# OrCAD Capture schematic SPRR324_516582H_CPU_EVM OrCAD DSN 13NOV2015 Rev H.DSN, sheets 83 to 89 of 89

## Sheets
83 SH14 - VAYU SD/MMC IF: size B; rev: A
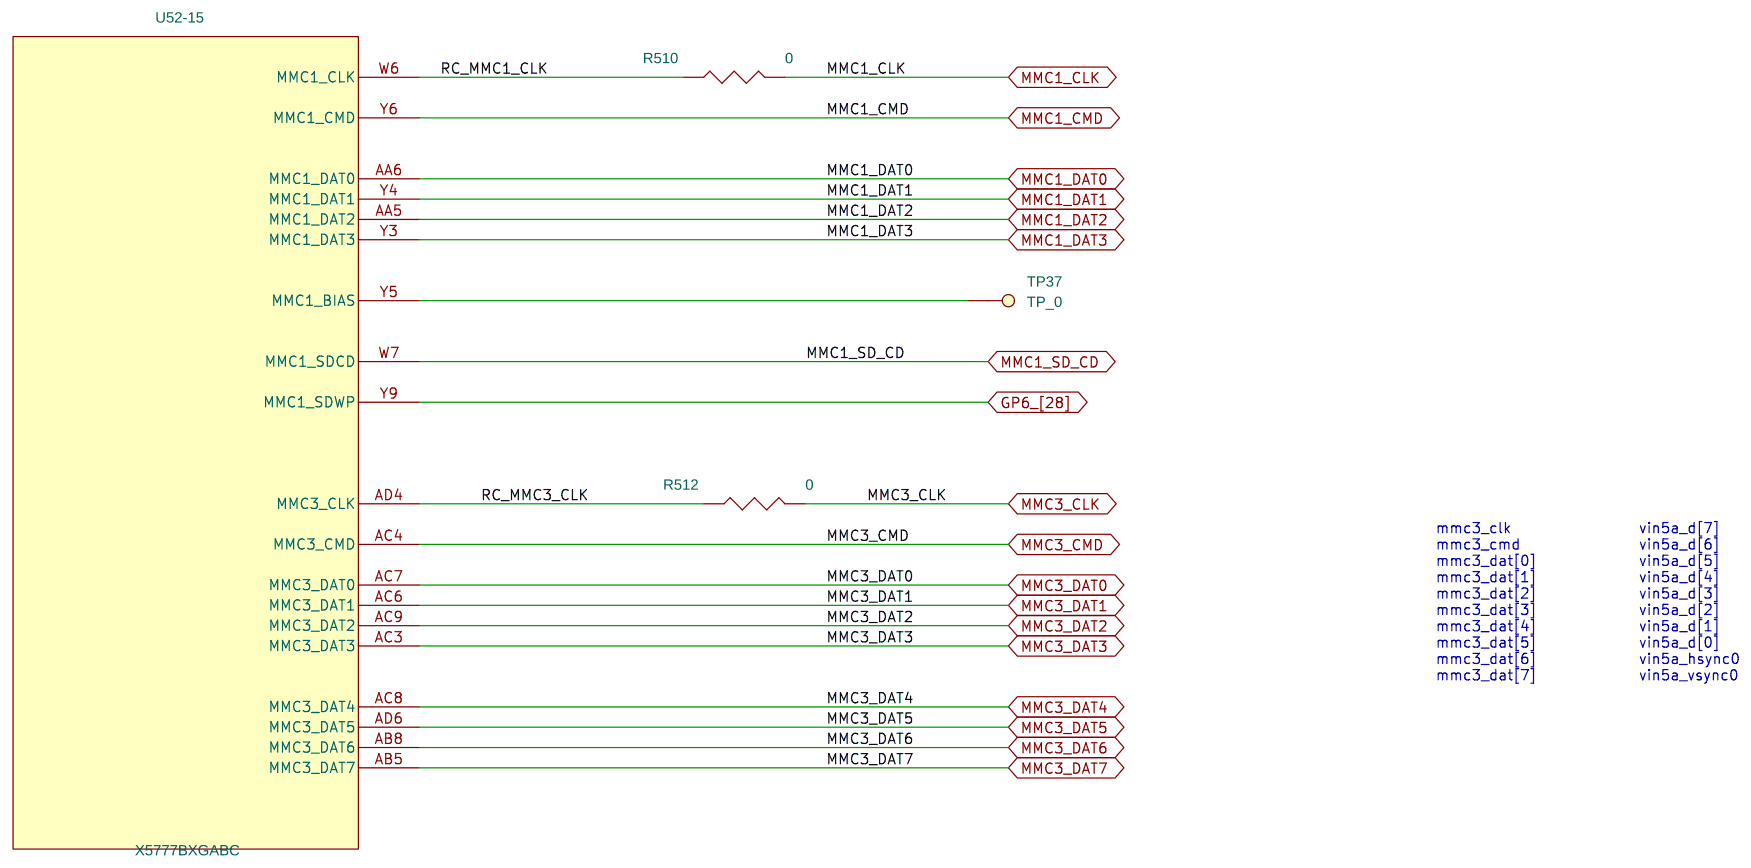
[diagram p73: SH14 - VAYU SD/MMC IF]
84 SH05 - SERIAL I/O MUX: size B; rev: E
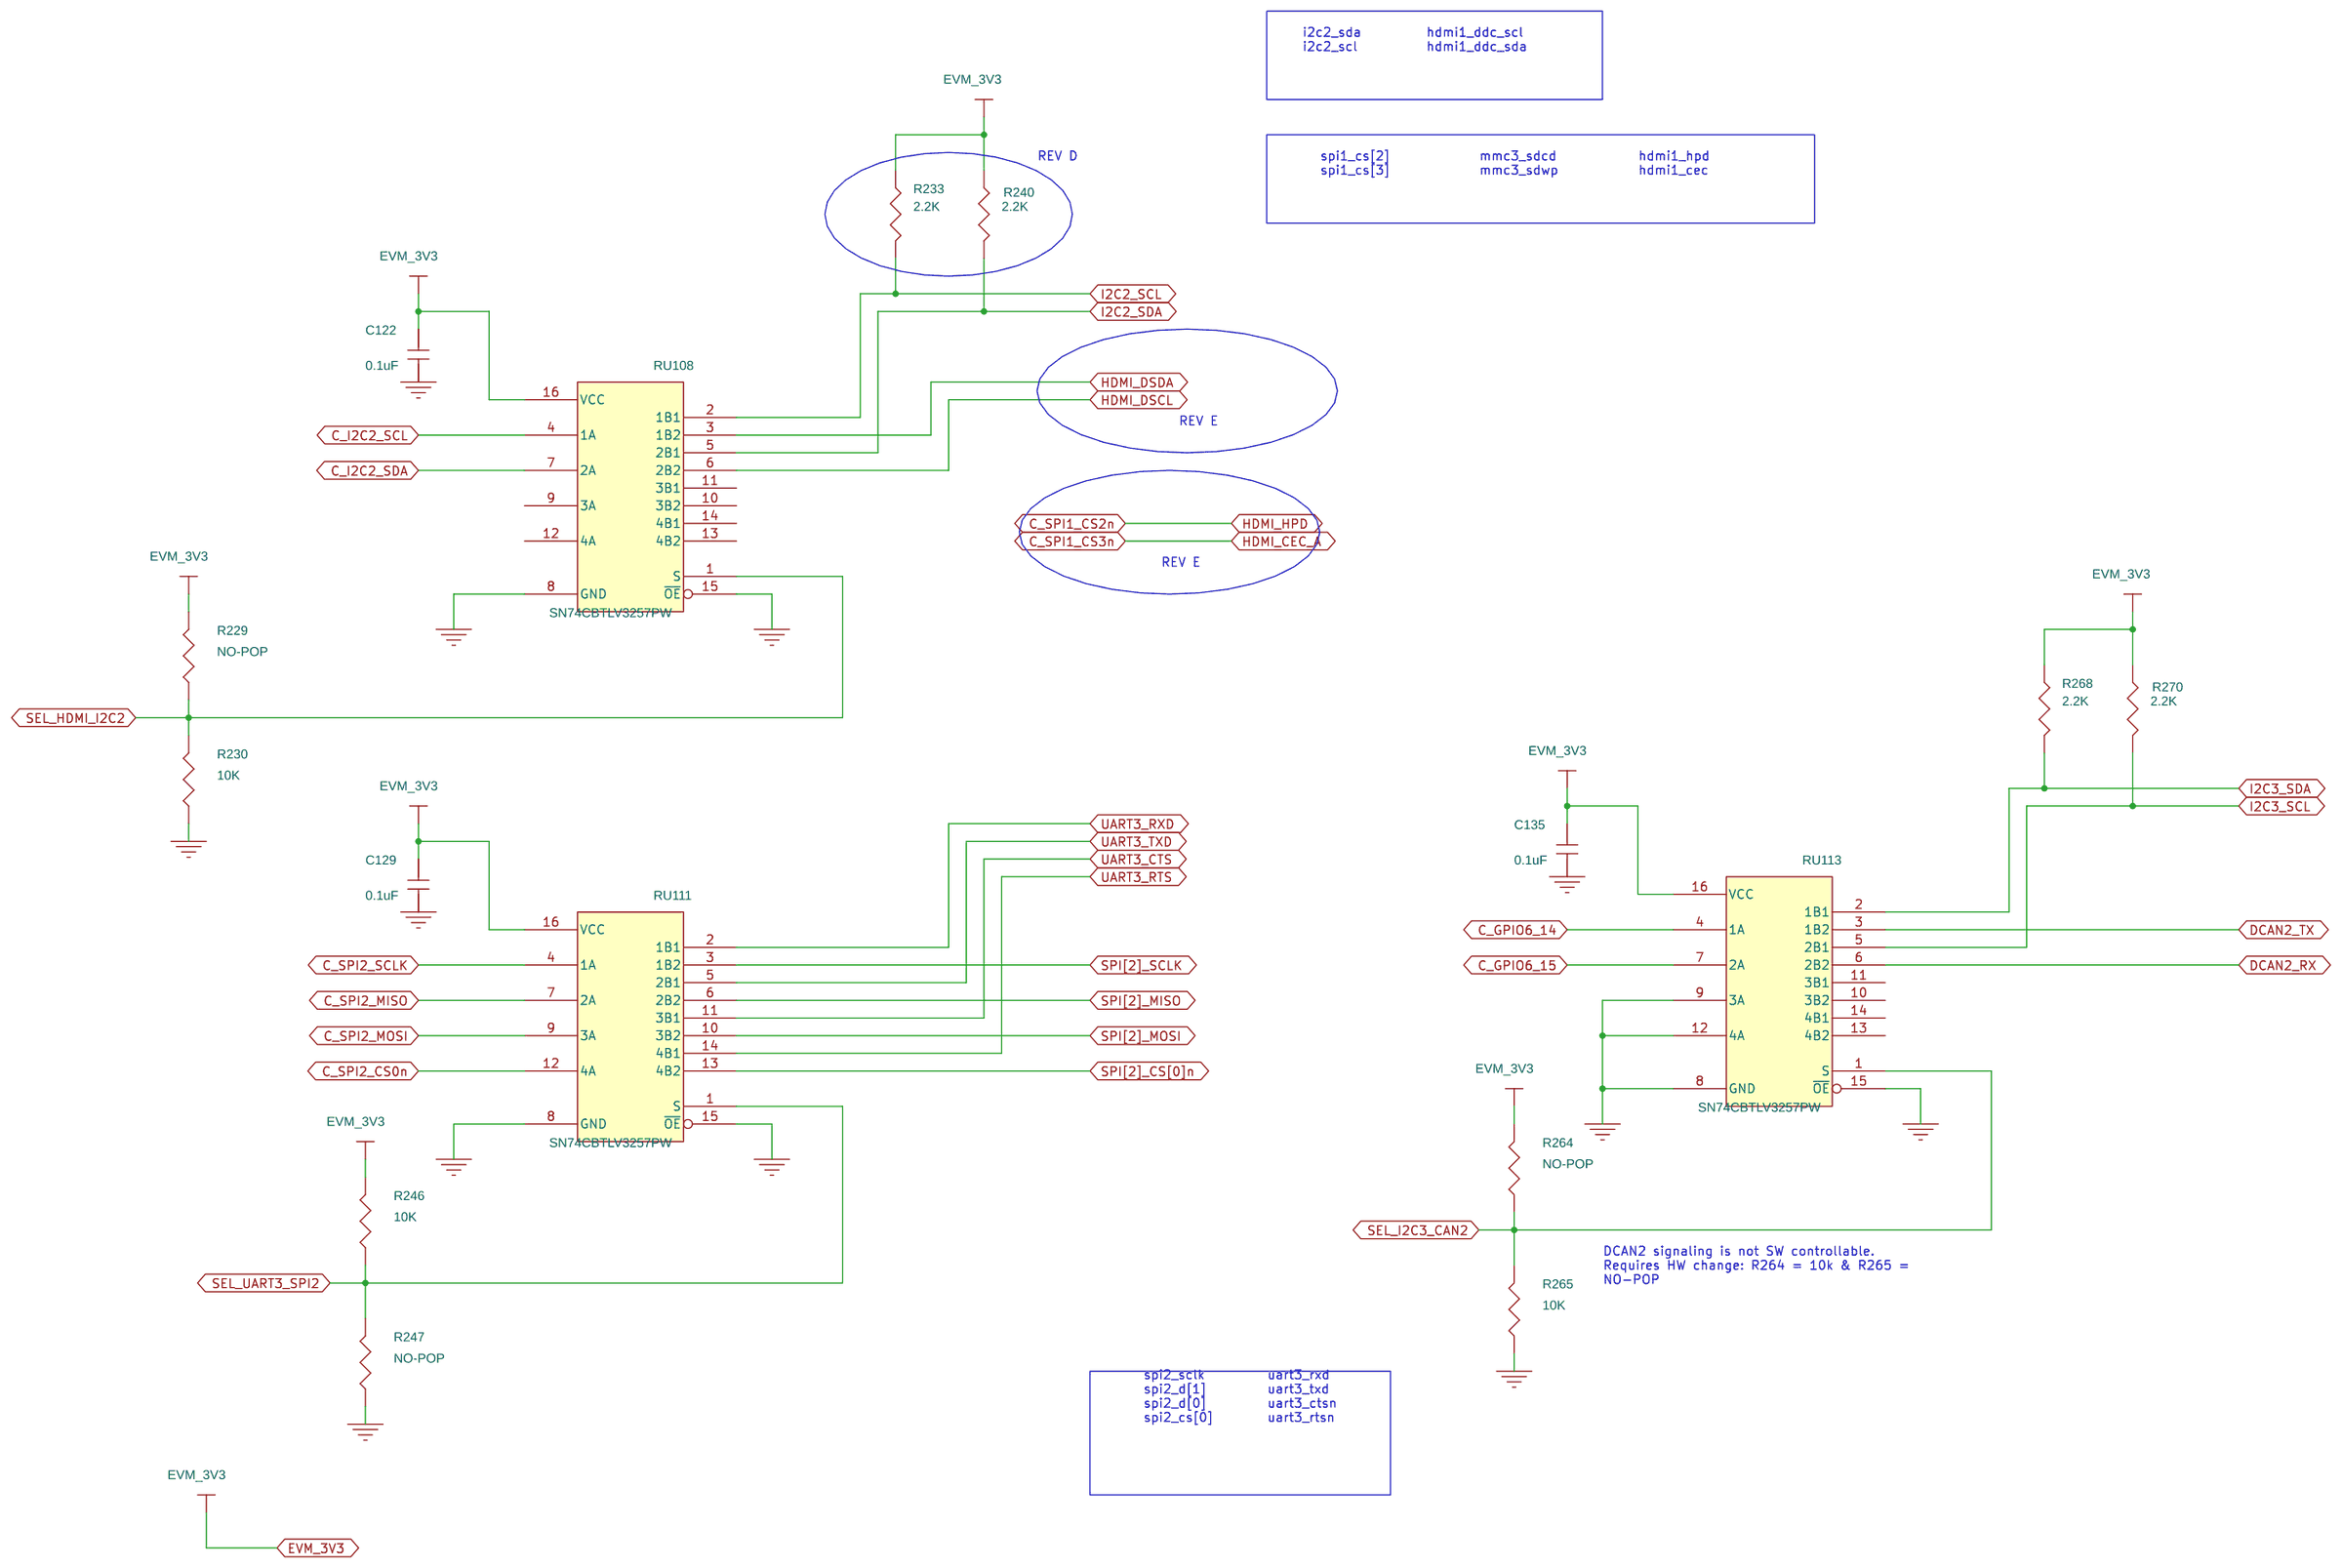
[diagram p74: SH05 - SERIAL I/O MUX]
85 SH18 - ENET0/VIN4 MUX: size B; rev: A
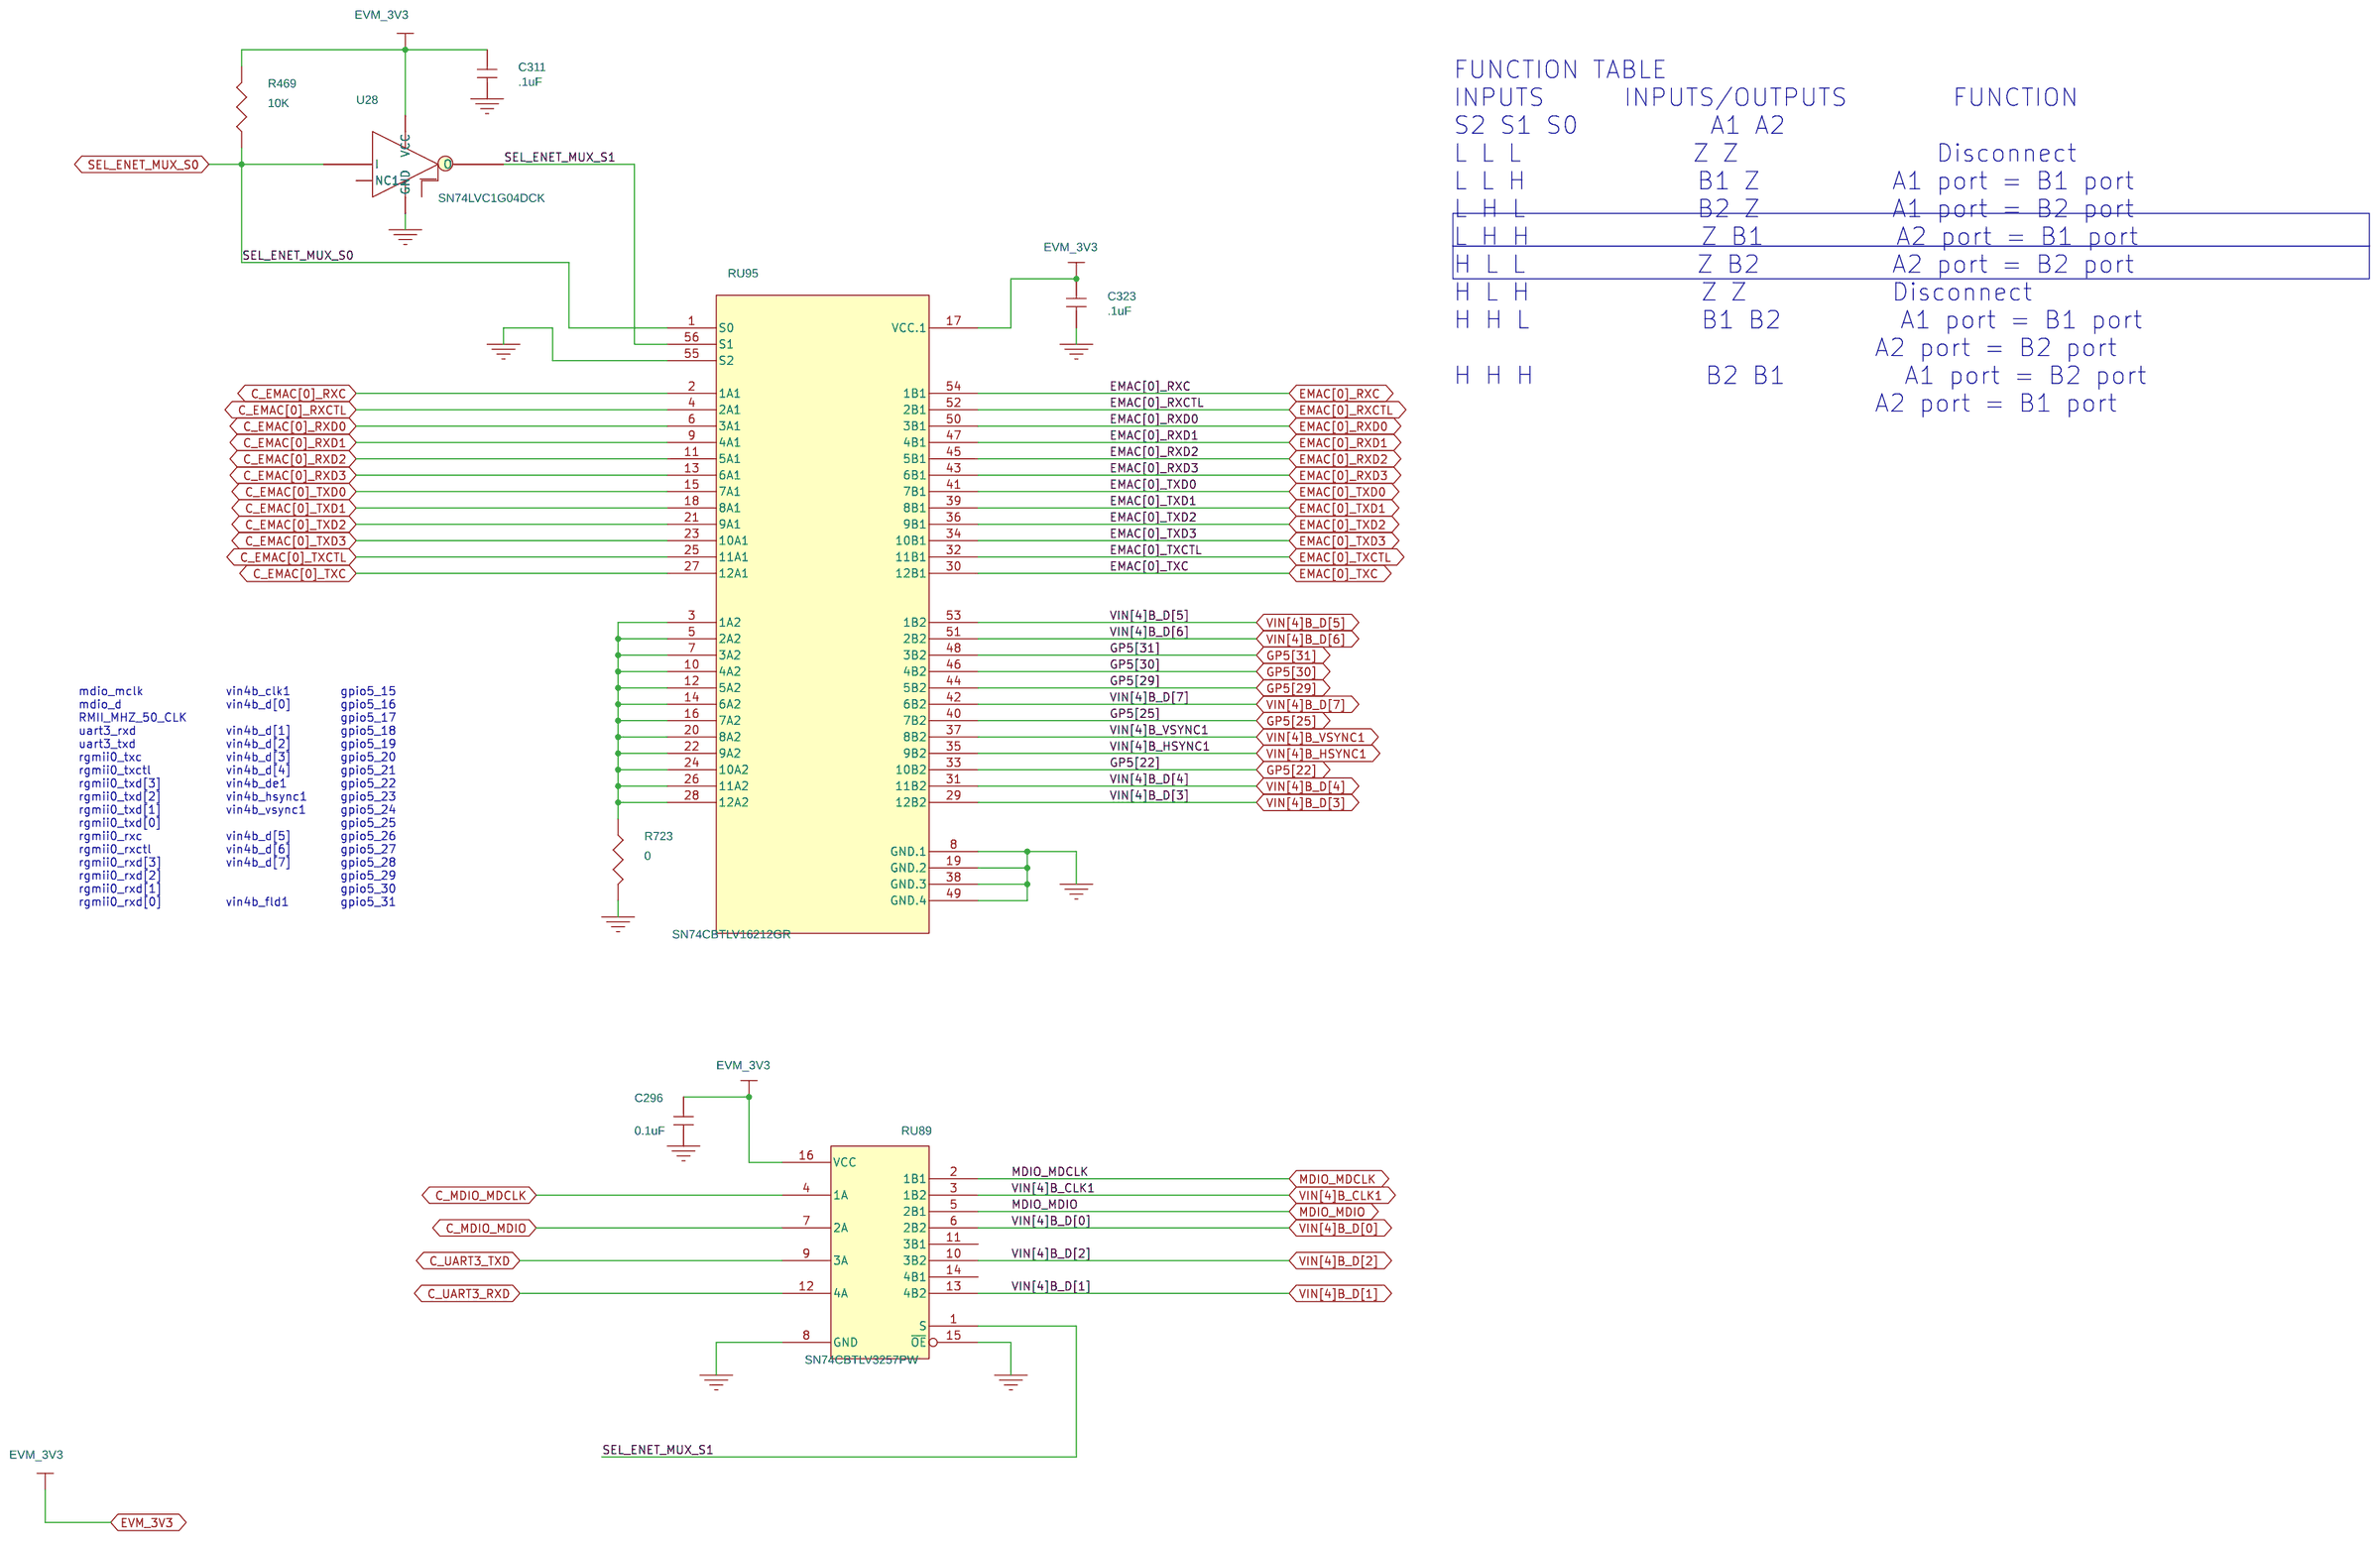
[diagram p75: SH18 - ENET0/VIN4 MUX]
86 SH03 - MCASP/VIN6A MUX: size B; rev: A
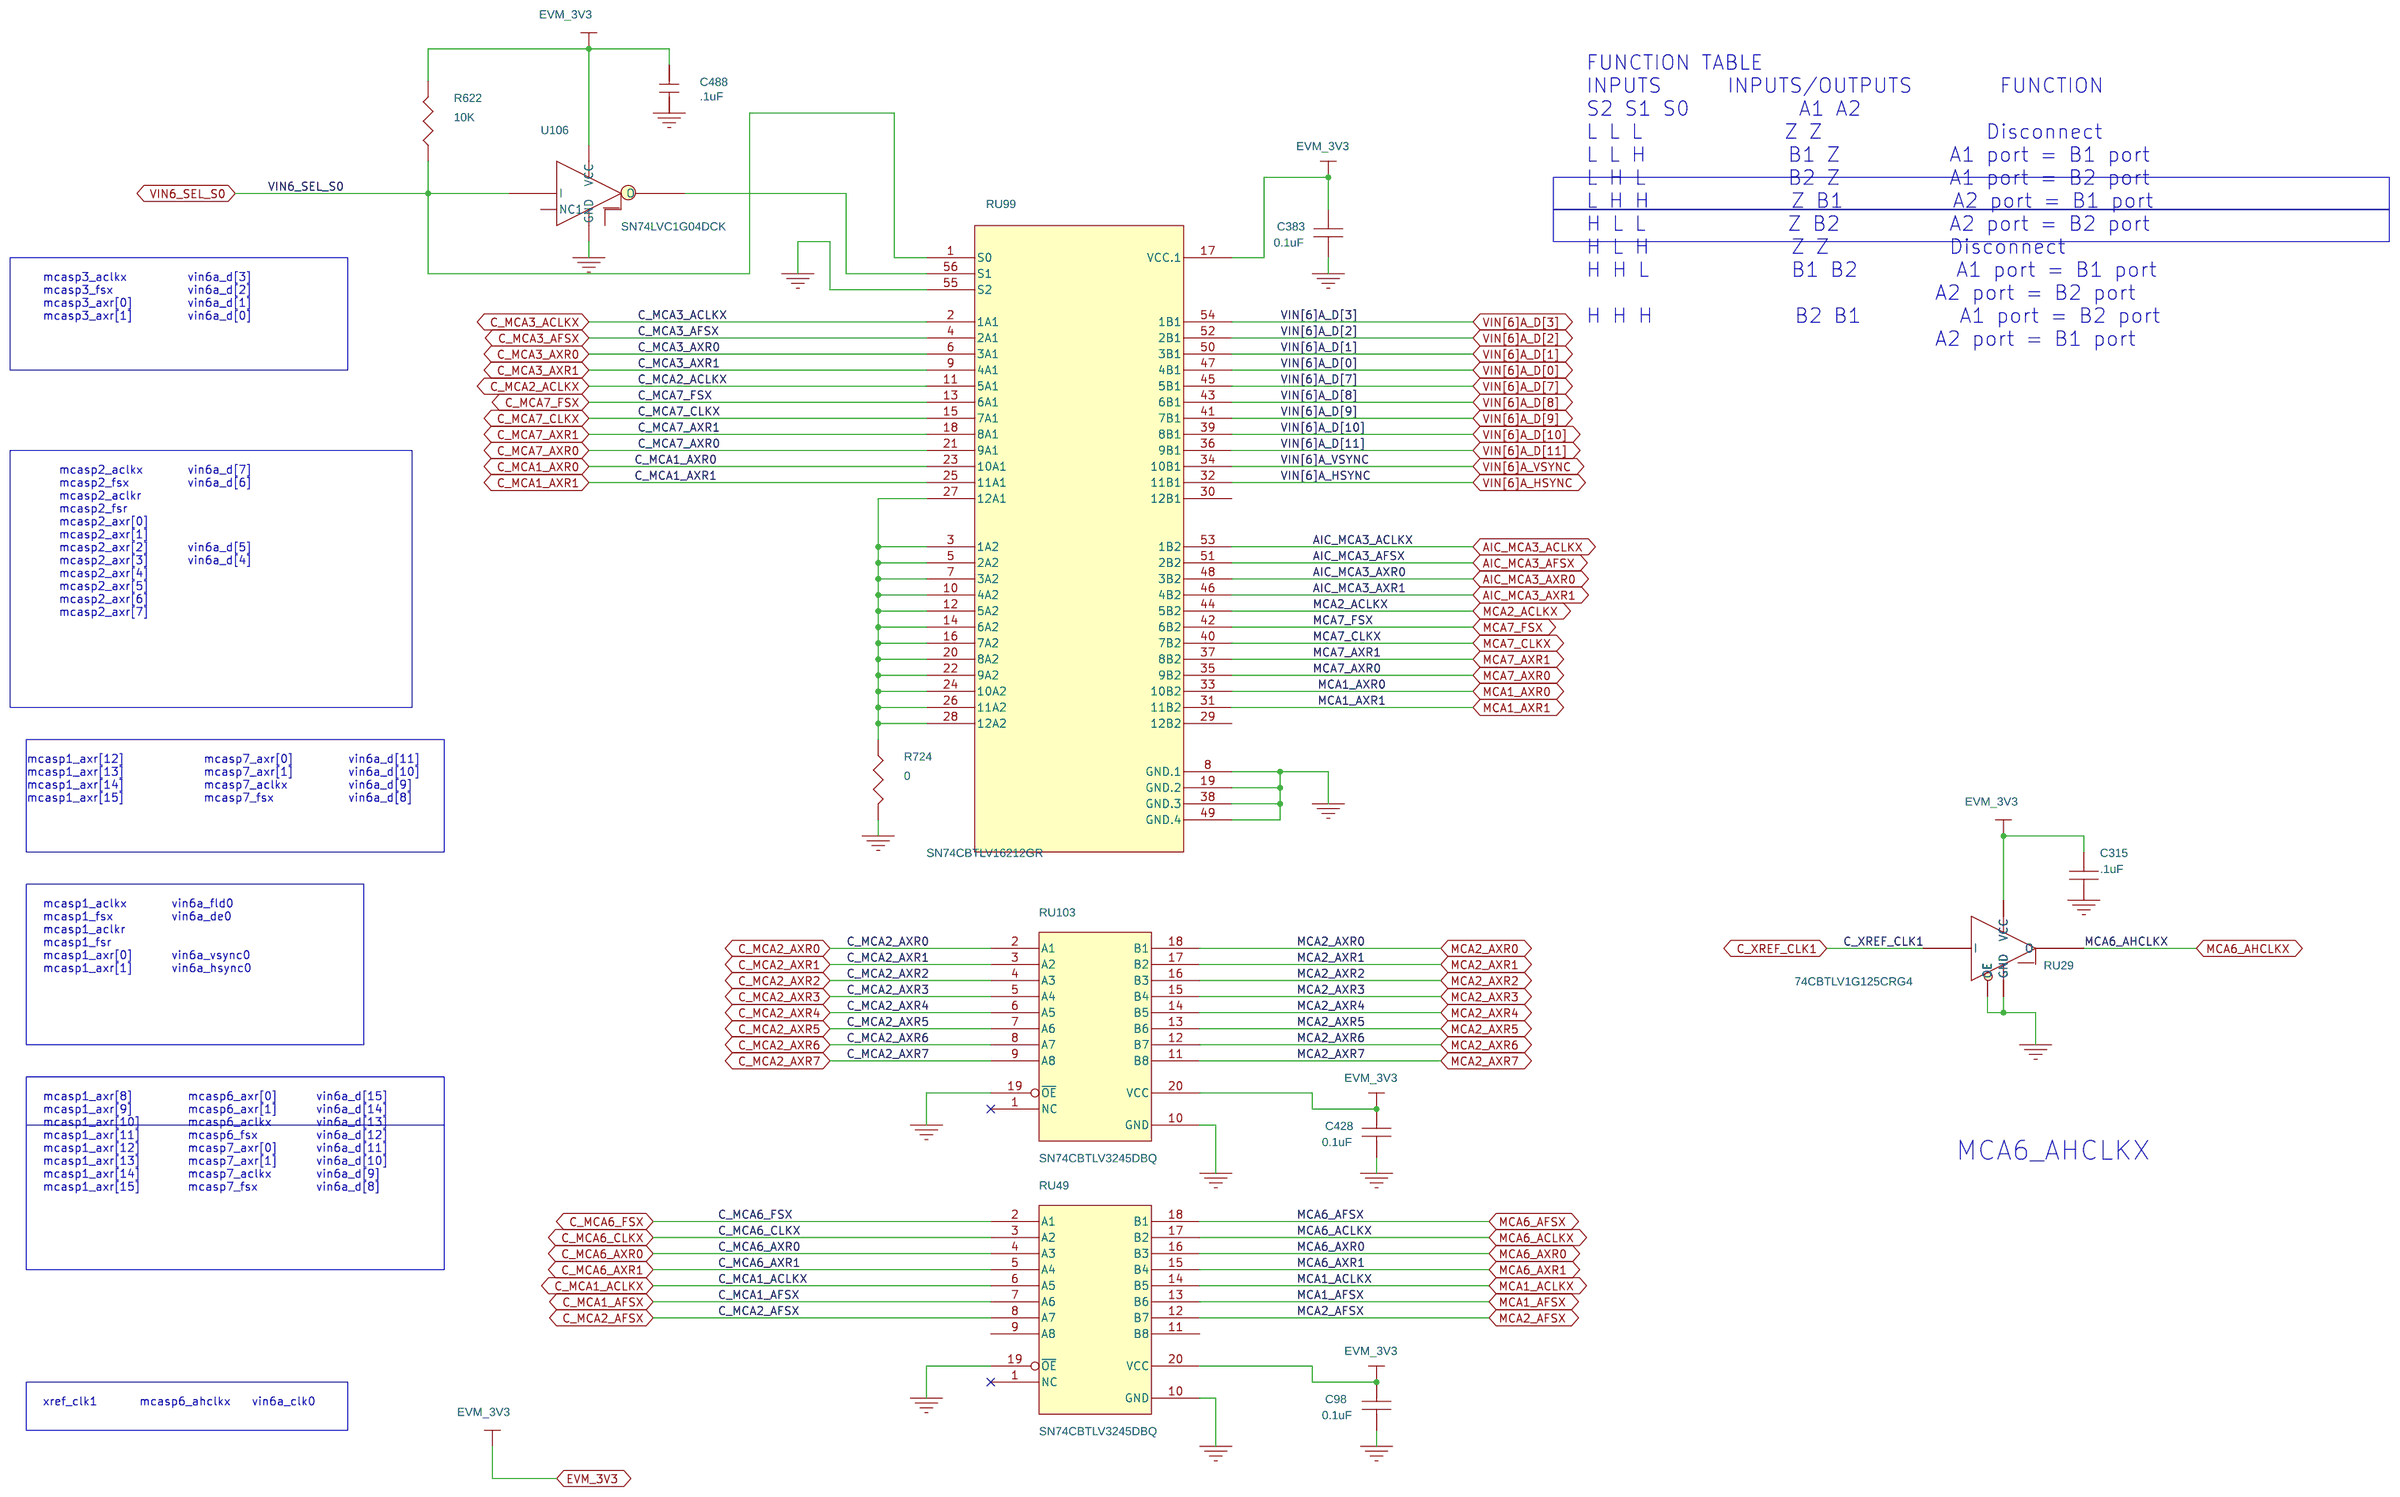
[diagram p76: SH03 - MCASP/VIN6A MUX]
87 SH04 - VAYU SERIAL I/O: size B; rev: D
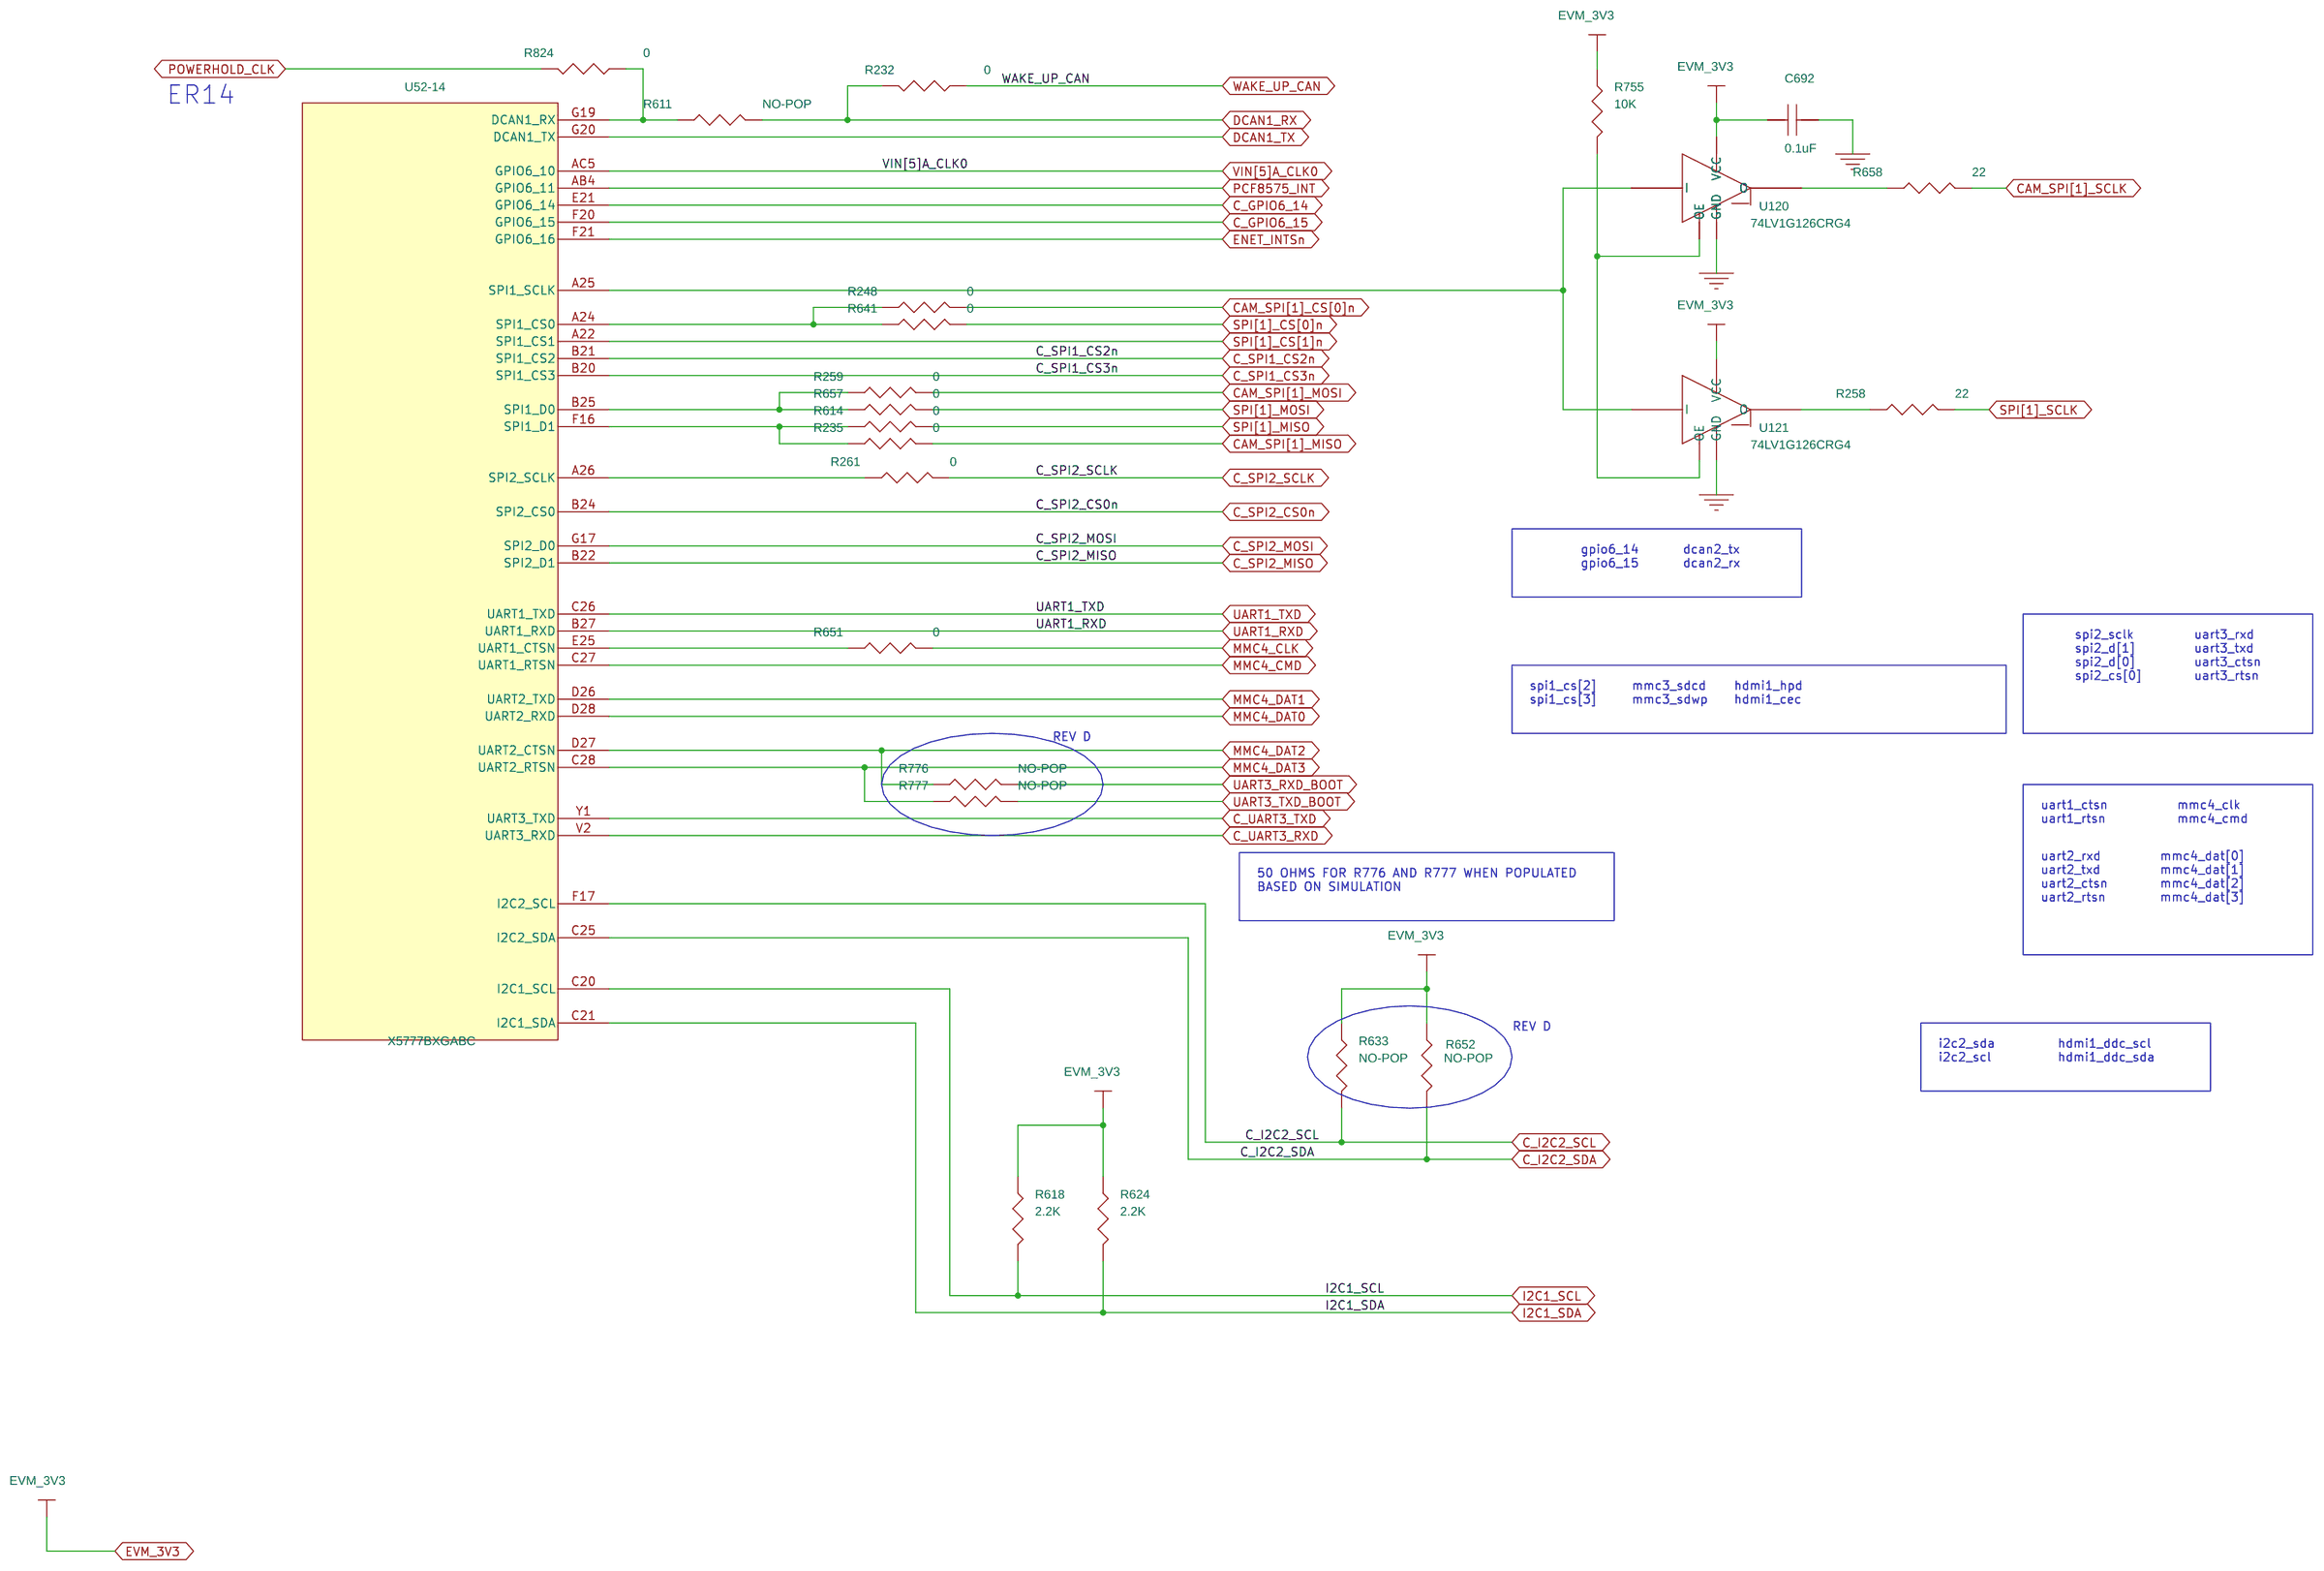
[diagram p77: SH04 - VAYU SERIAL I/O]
88 SH08 - I2C EEPROM/TEMP SENSOR: size B; rev: B
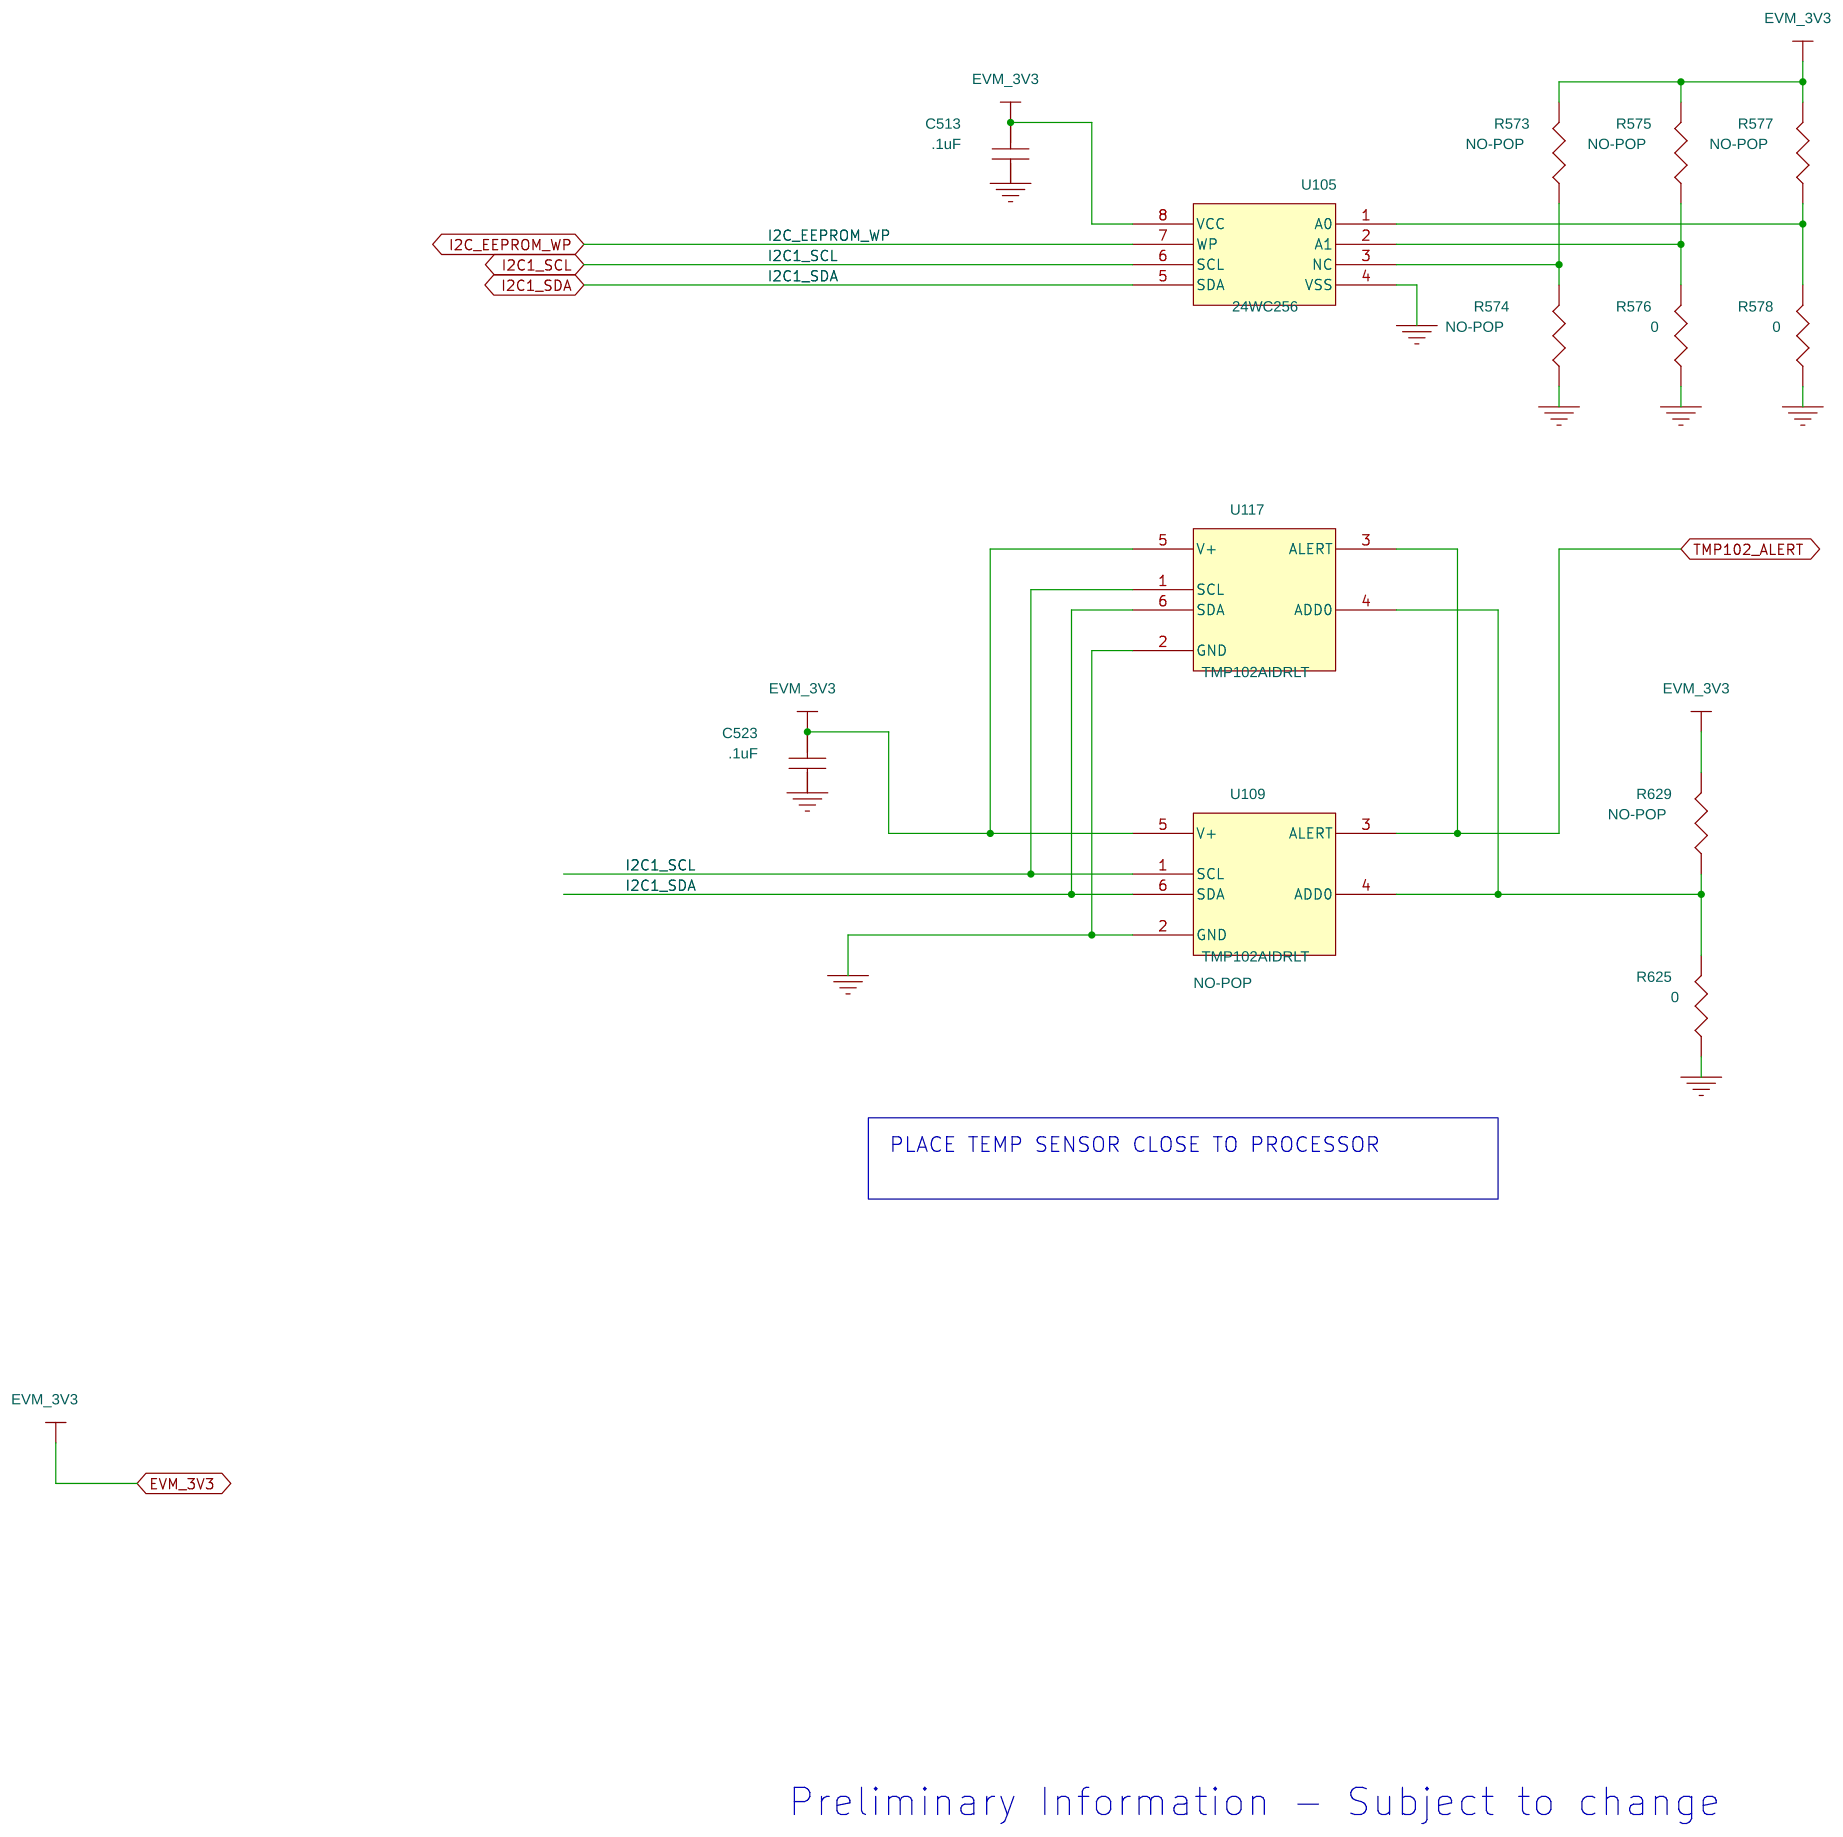
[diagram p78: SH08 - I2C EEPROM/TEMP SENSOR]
89 SH37 - VAYU SATA/PCIe INTERFACE: size B; rev: F
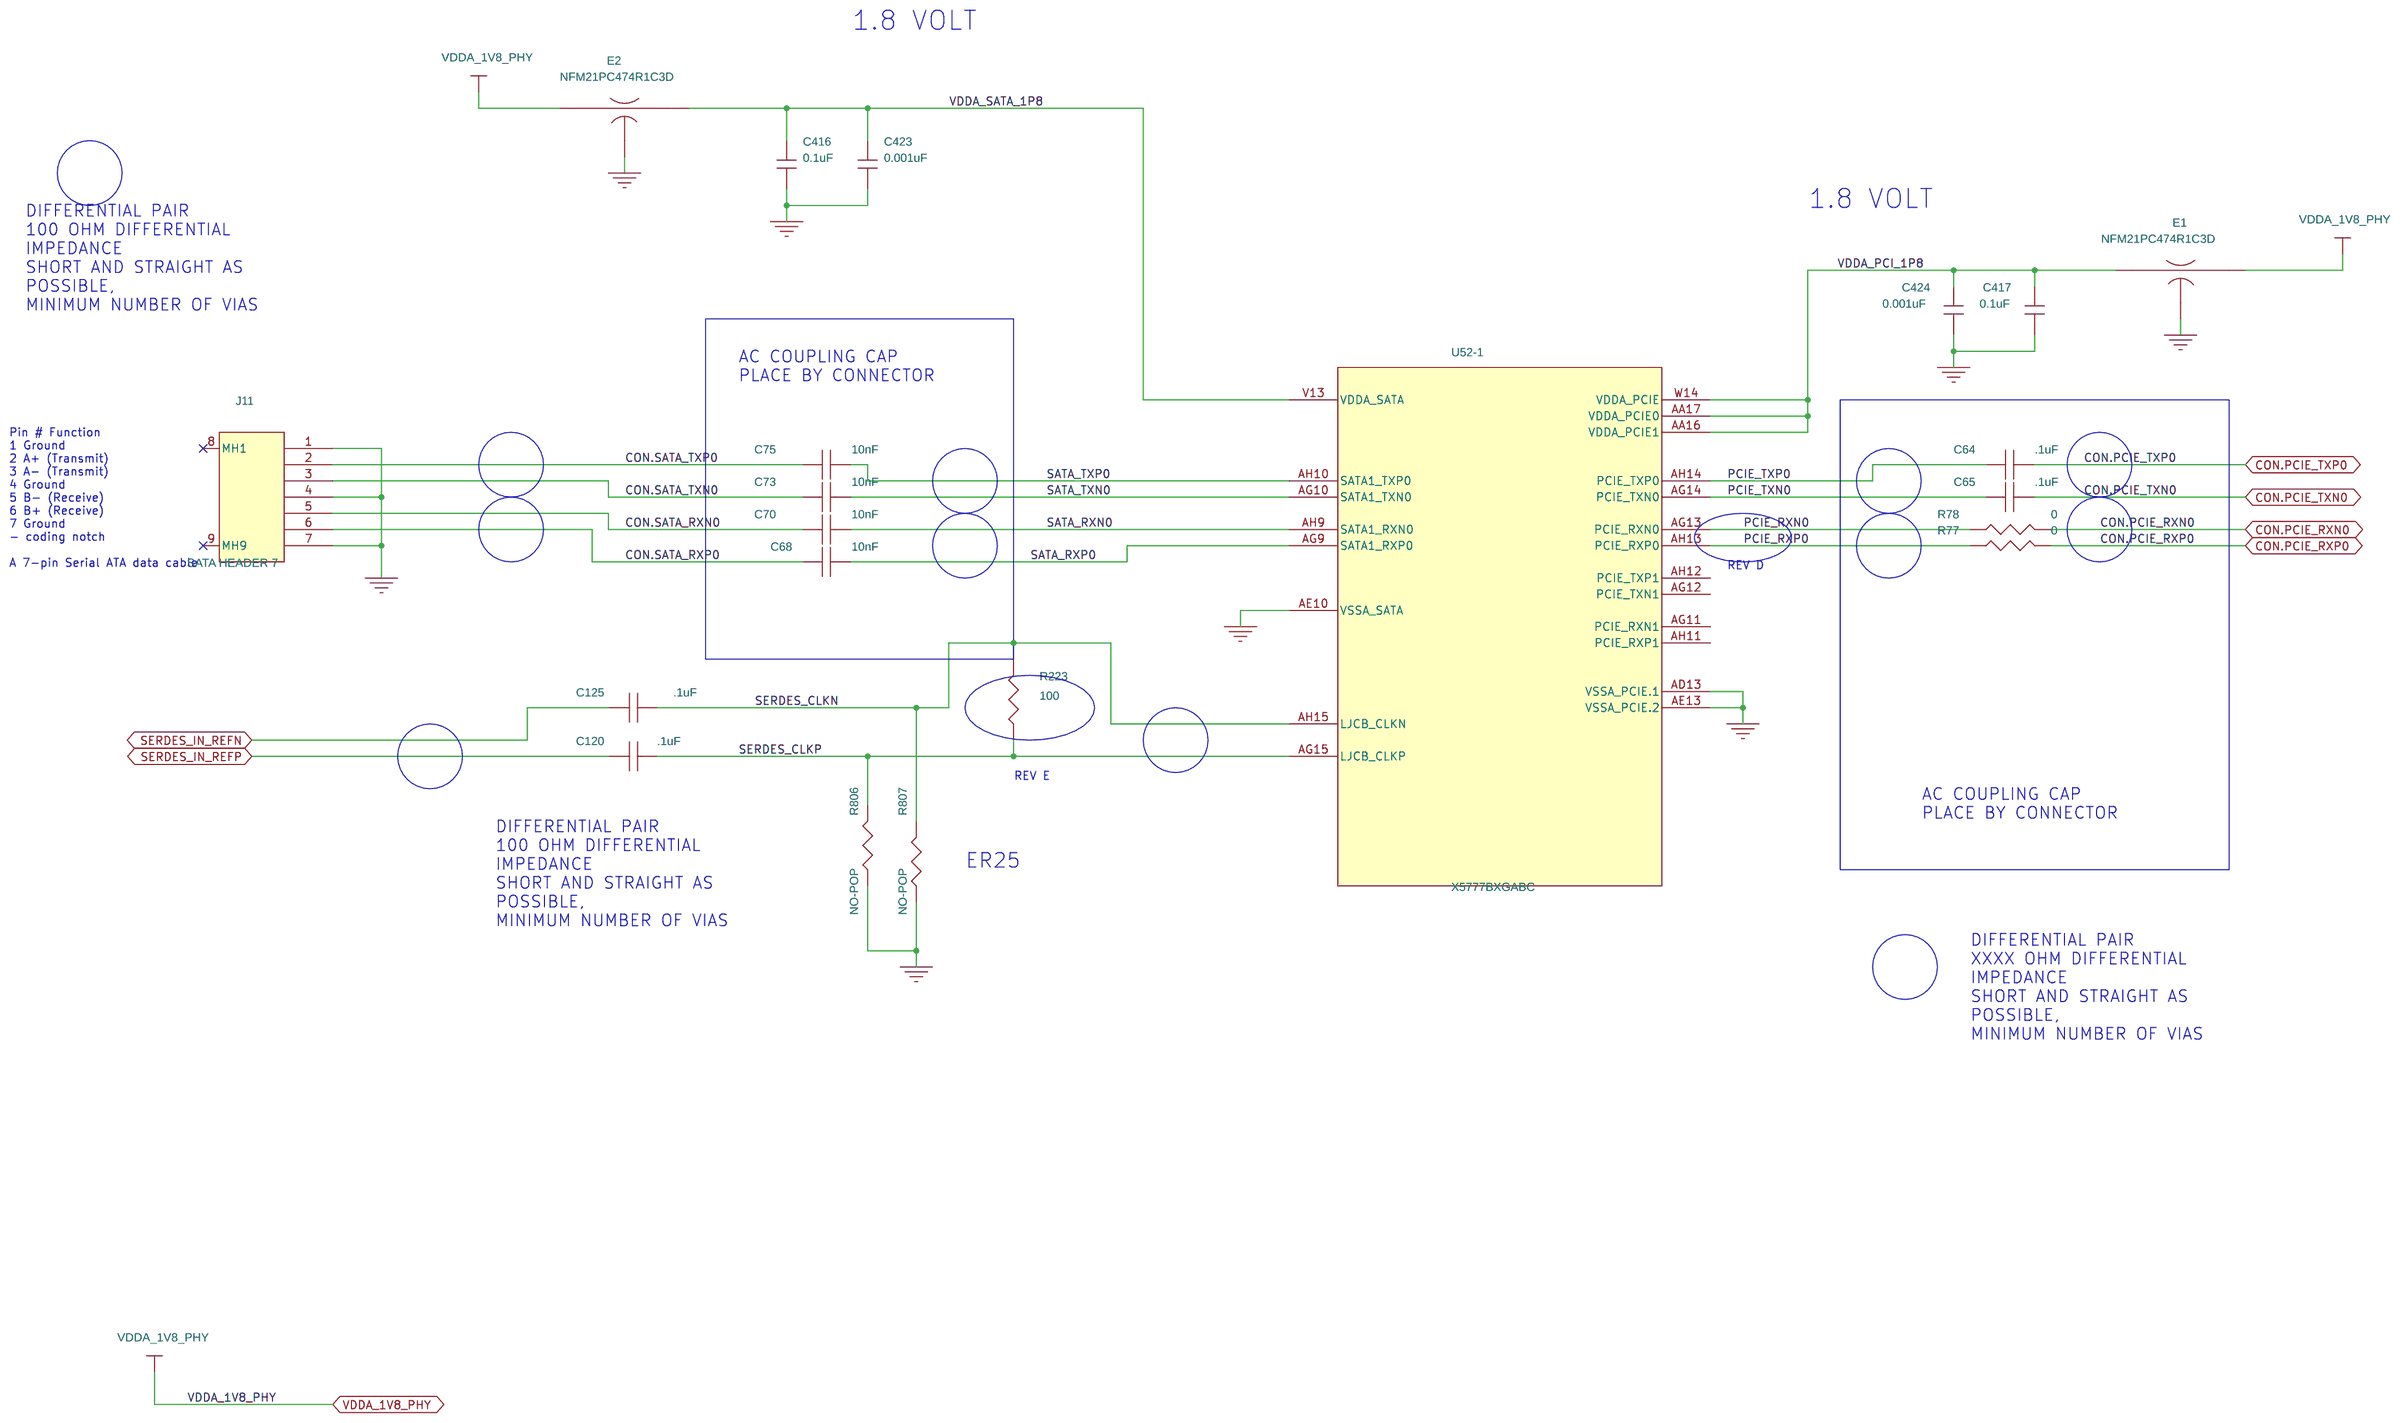
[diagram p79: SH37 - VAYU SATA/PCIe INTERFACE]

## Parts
sheet SH03 - MCASP/VIN6A MUX
C98  0.1uF  [c402-25]
C315  .1uF  [c402-25]
C383  0.1uF  [c402-25]
C428  0.1uF  [c402-25]
C488  .1uF  [c402-25]
R622  10K  [r201-6p6spc]
R724  0  [r201-6p6spc]
RU29  74CBTLV1G125CRG4  [dck-5]
RU49  SN74CBTLV3245DBQ  [dbq20-14X70]
RU99  SN74CBTLV16212GR  [dgg56-12x80]
RU103  SN74CBTLV3245DBQ  [dbq20-14X70]
U106  SN74LVC1G04DCK  [dck-5]
sheet SH04 - VAYU SERIAL I/O
C692  0.1uF  [c402-25]
R232  0  [r201-6p6spc]
R235  0  [r201-6p6spc]
R248  0  [r201-6p6spc]
R258  22  [r201-6p6spc]
R259  0  [r201-6p6spc]
R261  0  [r201-6p6spc]
R611  NO-POP  [r201-6p6spc]
R614  0  [r201-6p6spc]
R618  2.2K  [r402-25]
R624  2.2K  [r402-25]
R633  NO-POP  [r402-25]
R641  0  [r201-6p6spc]
R651  0  [r201-6p6spc]
R652  NO-POP  [r402-25]
R657  0  [r201-6p6spc]
R658  22  [r201-6p6spc]
R755  10K  [r402-25]
R776  NO-POP  [r201-6p6spc]
R777  NO-POP  [r201-6p6spc]
R824  0  [r201-6p6spc]
U120  74LV1G126CRG4  [dck-5]
U121  74LV1G126CRG4  [dck-5]
sheet SH05 - SERIAL I/O MUX
C122  0.1uF  [c402-25]
C129  0.1uF  [c402-25]
C135  0.1uF  [c402-25]
R229  NO-POP  [r201-6p6spc]
R230  10K  [r201-6p6spc]
R233  2.2K  [r402-25]
R240  2.2K  [r402-25]
R246  10K  [r201-6p6spc]
R247  NO-POP  [r201-6p6spc]
R264  NO-POP  [r201-6p6spc]
R265  10K  [r201-6p6spc]
R268  2.2K  [r402-25]
R270  2.2K  [r402-25]
RU108  SN74CBTLV3257PW  [tssop16-14x70]
RU111  SN74CBTLV3257PW  [tssop16-14x70]
RU113  SN74CBTLV3257PW  [tssop16-14x70]
sheet SH08 - I2C EEPROM/TEMP SENSOR
C513  .1uF  [c402-25]
C523  .1uF  [c402-25]
R573  NO-POP  [r402-25]
R574  NO-POP  [r402-25]
R575  NO-POP  [r402-25]
R576  0  [r402-25]
R577  NO-POP  [r402-25]
R578  0  [r402-25]
R625  0  [r402-25]
R629  NO-POP  [r402-25]
U105  24WC256  [so8-25x75-295]
U109  TMP102AIDRLT  [drl6-12x30]
U117  TMP102AIDRLT  [drl6-12x30]
sheet SH14 - VAYU SD/MMC IF
R510  0  [r201-6p6spc]
R512  0  [r201-6p6spc]
TP37  TP_0  [tp1-18rd8]
sheet SH18 - ENET0/VIN4 MUX
C296  0.1uF  [c402-25]
C311  .1uF  [c402-25]
C323  .1uF  [c402-25]
R469  10K  [r201-6p6spc]
R723  0  [r201-6p6spc]
RU89  SN74CBTLV3257PW  [tssop16-14x70]
RU95  SN74CBTLV16212GR  [dgg56-12x80]
U28  SN74LVC1G04DCK  [dck-5]
sheet SH28 - VAYU VOUT1 PORT LCD
U52  X5777BXGABC  [sktbga-zkk-6334-p760]  (sections -1,-10,-11,-12,-13,-14,-15,-16,-17,-18,-19,-2,-20,-21,-22,-23,-3,-4,-5,-6,-7,-8,-9)
sheet SH37 - VAYU SATA/PCIe INTERFACE
C64  .1uF  [c402-25]
C65  .1uF  [c402-25]
C68  10nF  [c402-25]
C70  10nF  [c402-25]
C73  10nF  [c402-25]
C75  10nF  [c402-25]
C120  .1uF  [c603-35x45]
C125  .1uF  [c603-35x45]
C416  0.1uF  [c201-18p5x15]
C417  0.1uF  [c201-18p5x15]
C423  0.001uF  [c201-18p5x15]
C424  0.001uF  [c201-18p5x15]
E1  NFM21PC474R1C3D  [emi-NFM21p]
E2  NFM21PC474R1C3D  [emi-NFM21p]
J11  SATA HEADER 7  [molex-67491-002]
R77  0  [r402-25]
R78  0  [r402-25]
R223  100  [r402-25]
R806  NO-POP  [r201-6p6spc]
R807  NO-POP  [r201-6p6spc]

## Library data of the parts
C98 C383 C428 = CAP: Part #: 101587-1100R
C315 = CAP_NP_2: Part #: 101587-1100R
C122 C129 C135 C296 C311 C323 C488 = CAP_NP: Part #: 101587-1100R
R230 R246 R265 R469 R622 = R: Part #: 103158-1003R
R232 R235 R248 R259 R261 R510 R512 R614 R641 R651 R657 R723 R724 R824 = R: Part #: 103158-0001R
RU29 = SN74LVC1G125: Part #: 101689-0125R
RU49 = 74PCT245_3: Part #: 101659-0001R; SD PCB Footprint: PSOP20PW
RU95 RU99 = SN74CBT16212DGGR: Part #: 102693-0001R
RU103 = 74PCT245_3: Part #: 101659-0001R
U28 U106 = SN74LVC1GU04_1: Part #: 101057-0004R
C692 = CAP_NP_1: Part #: 101587-1100R
R258 R658 = R: Part #: 103158-2200R
R229 R247 R264 R611 R776 R777 R806 R807 = R: Part #: R0201-NOPOP
R233 R240 R268 R270 R618 R624 = R: Part #: 101370-2202R
R633 R652 = R: Part #: r0402-nopop
R755 = R: Part #: 101370-1003R
U120 U121 = SN74LVC1G125_0: Part #: 101057-0126R
RU89 RU108 RU111 RU113 = SN74CBT3257PW: Part #: 101670-0001R
C64 C65 C513 C523 = CAP_.1_uF_10%_0603: Part #: 101587-1100R
R573-R575 R577 R629 = R: Part #: R0402-NOPOP
R576 R578 R625 = R_1: Part #: 101370-0001R
U105 = 24WC256: Part #: 102235-0001R
U109 = TMP102AIDRLT: Part #: NO-POP
U117 = TMP102AIDRLT: Part #: 104192-0001R
TP37 = TP_0: Part #: TP-18RD8-NO-POP
U52 = VAYU_DEC_3_2: Part #: 104183-0003R
C68 C70 C73 C75 = CAP_.1_uF_10%_0603: Part #: 101587-1101R
C120 C125 = CAP_.1_uF_10%_0603: Part #: 100994-1100R
C416 C417 = CAP_NP: Part #: 103241-1100R
C423 C424 = CAP_NP: Part #: 103367-1102R
E1 E2 = NFM_1: Part #: 102569-1470R
J11 = HEADER_7_0: Part #: 102930-0007R
R77 R78 = R: Part #: 101370-0001R
R223 = R: Part #: 101370-1001R

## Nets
GND: C98.2 C122.2 C129.2 C135.2 C296.2 C311.2 C315.2 C323.2 C383.2 C416.2 C417.2 C423.2 C424.2 C428.2 C488.2 C513.1 C523.1 C692.2 E1.2 E2.2 J11.1 J11.4 J11.7 R230.2 R247.2 R265.2 R574.2 R576.2 R578.2 R625.2 R723.2 R724.2 R806.2 R807.2 RU29.1(OE) RU29.3(GND) RU49.10(GND) RU49.19(~{OE}) RU89.8(GND) RU89.15(~{OE}) RU95.8(GND.1) RU95.19(GND.2) RU95.38(GND.3) RU95.49(GND.4) RU95.55(S2) RU99.8(GND.1) RU99.19(GND.2) RU99.38(GND.3) RU99.49(GND.4) RU99.55(S2) RU103.10(GND) RU103.19(~{OE}) RU108.8(GND) RU108.15(~{OE}) RU111.8(GND) RU111.15(~{OE}) RU113.8(GND) RU113.9(3A) RU113.12(4A) RU113.15(~{OE}) U28.3(GND) U52.AD13(VSSA_PCIE.1) U52.AE10(VSSA_SATA) U52.AE13(VSSA_PCIE.2) U105.4(VSS) U106.3(GND) U109.2(GND) U117.2(GND) U120.3(GND) U121.3(GND) ; also on sheet 3 4 5 7 8 9 10 11 13 15 16 17 18 19 20 21 24 25 26 27 28 29 30 31 32 33 34 35 36 37 38 39 40 42 43 46 47 49 50 51 52 53 54 55 56 57 58 60 61 62 63 64 65 66 67 68 69 70 71 72 73 74 75 77 79 80 81
VDDA_1V8_PHY: E1.3 E2.3 ; also on sheet 13 21 75
VDDA_PCI_1P8: C417.1 C424.1 E1.1 U52.AA16(VDDA_PCIE1) U52.AA17(VDDA_PCIE0) U52.W14(VDDA_PCIE)
VDDA_SATA_1P8: C416.1 C423.1 E2.1 U52.V13(VDDA_SATA)
VIN6_SEL_S0: R622.2 RU99.1(S0) U106.2(I) ; also on sheet 9
VIN[4]B_CLK1: RU89.3(1B2) ; also on sheet 60
VIN[4]B_D[0]: RU89.6(2B2) ; also on sheet 60
VIN[4]B_D[1]: RU89.13(4B2) ; also on sheet 60
VIN[4]B_D[2]: RU89.10(3B2) ; also on sheet 60
VIN[4]B_D[3]: RU95.29(12B2) ; also on sheet 60
VIN[4]B_D[4]: RU95.31(11B2) ; also on sheet 60
VIN[4]B_D[5]: RU95.53(1B2) ; also on sheet 60
VIN[4]B_D[6]: RU95.51(2B2) ; also on sheet 60
VIN[4]B_D[7]: RU95.42(6B2) ; also on sheet 60
VIN[4]B_HSYNC1: RU95.35(9B2) ; also on sheet 60
VIN[4]B_VSYNC1: RU95.37(8B2) ; also on sheet 60
VIN[5]A_CLK0: U52.AC5(GPIO6_10) ; also on sheet 60
VIN[6]A_D[0]: RU99.47(4B1) ; also on sheet 61
VIN[6]A_D[1]: RU99.50(3B1) ; also on sheet 61
VIN[6]A_D[2]: RU99.52(2B1) ; also on sheet 61
VIN[6]A_D[3]: RU99.54(1B1) ; also on sheet 61
VIN[6]A_D[7]: RU99.45(5B1) ; also on sheet 61
VIN[6]A_D[8]: RU99.43(6B1) ; also on sheet 61
VIN[6]A_D[9]: RU99.41(7B1) ; also on sheet 61
VIN[6]A_D[10]: RU99.39(8B1) ; also on sheet 61
VIN[6]A_D[11]: RU99.36(9B1) ; also on sheet 61
VIN[6]A_HSYNC: RU99.32(11B1) ; also on sheet 61
VIN[6]A_VSYNC: RU99.34(10B1) ; also on sheet 61
AIC_MCA3_ACLKX: RU99.53(1B2) ; also on sheet 55
AIC_MCA3_AFSX: RU99.51(2B2) ; also on sheet 55
AIC_MCA3_AXR0: RU99.48(3B2) ; also on sheet 55
AIC_MCA3_AXR1: RU99.46(4B2) ; also on sheet 55
C_EMAC[0]_RXC: RU95.2(1A1) ; also on sheet 12
C_EMAC[0]_RXCTL: RU95.4(2A1) ; also on sheet 12
C_EMAC[0]_RXD0: RU95.6(3A1) ; also on sheet 12
C_EMAC[0]_RXD1: RU95.9(4A1) ; also on sheet 12
C_EMAC[0]_RXD2: RU95.11(5A1) ; also on sheet 12
C_EMAC[0]_RXD3: RU95.13(6A1) ; also on sheet 12
C_EMAC[0]_TXC: RU95.27(12A1) ; also on sheet 12
C_EMAC[0]_TXCTL: RU95.25(11A1) ; also on sheet 12
C_EMAC[0]_TXD0: RU95.15(7A1) ; also on sheet 12
C_EMAC[0]_TXD1: RU95.18(8A1) ; also on sheet 12
C_EMAC[0]_TXD2: RU95.21(9A1) ; also on sheet 12
C_EMAC[0]_TXD3: RU95.23(10A1) ; also on sheet 12
C_GPIO6_14: RU113.4(1A) U52.E21(GPIO6_14)
C_GPIO6_15: RU113.7(2A) U52.F20(GPIO6_15)
C_I2C2_SCL: R633.2 RU108.4(1A) U52.F17(I2C2_SCL)
C_I2C2_SDA: R652.2 RU108.7(2A) U52.C25(I2C2_SDA)
C_MCA1_ACLKX: RU49.6(A5) ; also on sheet 2
C_MCA1_AFSX: RU49.7(A6) ; also on sheet 2
C_MCA1_AXR0: RU99.23(10A1) ; also on sheet 2
C_MCA1_AXR1: RU99.25(11A1) ; also on sheet 2
C_MCA2_ACLKX: RU99.11(5A1) ; also on sheet 2
C_MCA2_AFSX: RU49.8(A7) ; also on sheet 2
C_MCA2_AXR0: RU103.2(A1) ; also on sheet 2
C_MCA2_AXR1: RU103.3(A2) ; also on sheet 2
C_MCA2_AXR2: RU103.4(A3) ; also on sheet 2
C_MCA2_AXR3: RU103.5(A4) ; also on sheet 2
C_MCA2_AXR4: RU103.6(A5) ; also on sheet 2
C_MCA2_AXR5: RU103.7(A6) ; also on sheet 2
C_MCA2_AXR6: RU103.8(A7) ; also on sheet 2
C_MCA2_AXR7: RU103.9(A8) ; also on sheet 2
C_MCA3_ACLKX: RU99.2(1A1) ; also on sheet 2
C_MCA3_AFSX: RU99.4(2A1) ; also on sheet 2
C_MCA3_AXR0: RU99.6(3A1) ; also on sheet 2
C_MCA3_AXR1: RU99.9(4A1) ; also on sheet 2
C_MCA6_AXR0: RU49.4(A3) ; also on sheet 2
C_MCA6_AXR1: RU49.5(A4) ; also on sheet 2
C_MCA6_CLKX: RU49.3(A2) ; also on sheet 2
C_MCA6_FSX: RU49.2(A1) ; also on sheet 2
C_MCA7_AXR0: RU99.21(9A1) ; also on sheet 2
C_MCA7_AXR1: RU99.18(8A1) ; also on sheet 2
C_MCA7_CLKX: RU99.15(7A1) ; also on sheet 2
C_MCA7_FSX: RU99.13(6A1) ; also on sheet 2
C_MDIO_MDCLK: RU89.4(1A) ; also on sheet 12
C_MDIO_MDIO: RU89.7(2A) ; also on sheet 12
C_SPI1_CS2n: U52.B21(SPI1_CS2) ; also on sheet 27
C_SPI1_CS3n: U52.B20(SPI1_CS3) ; also on sheet 27
C_SPI2_CS0n: RU111.12(4A) U52.B24(SPI2_CS0)
C_SPI2_MISO: RU111.7(2A) U52.B22(SPI2_D1)
C_SPI2_MOSI: RU111.9(3A) U52.G17(SPI2_D0)
C_SPI2_SCLK: R261.1 RU111.4(1A)
C_UART3_RXD: RU89.12(4A) U52.V2(UART3_RXD)
C_UART3_TXD: RU89.9(3A) U52.Y1(UART3_TXD)
C_XREF_CLK1: RU29.2(I) ; also on sheet 2
CAM_SPI[1]_CS[0]n: R248.1 ; also on sheet 29
CAM_SPI[1]_MISO: R235.1 ; also on sheet 29
CAM_SPI[1]_MOSI: R259.1 ; also on sheet 29
CAM_SPI[1]_SCLK: R658.1 ; also on sheet 29
CON.PCIE_RXN0: R78.2 ; also on sheet 31
CON.PCIE_RXP0: R77.2 ; also on sheet 31
CON.PCIE_TXN0: C65.2 ; also on sheet 31
CON.PCIE_TXP0: C64.2 ; also on sheet 31
CON.SATA_RXN0: C70.1 J11.5
CON.SATA_RXP0: C68.1 J11.6
CON.SATA_TXN0: C73.1 J11.3
CON.SATA_TXP0: C75.1 J11.2
DCAN1_RX: R232.1 R611.1 ; also on sheet 3
DCAN1_TX: U52.G20(DCAN1_TX) ; also on sheet 3
DCAN2_RX: RU113.6(2B2) ; also on sheet 3
DCAN2_TX: RU113.3(1B2) ; also on sheet 3
EMAC[0]_RXC: RU95.54(1B1) ; also on sheet 56
EMAC[0]_RXCTL: RU95.52(2B1) ; also on sheet 56
EMAC[0]_RXD0: RU95.50(3B1) ; also on sheet 56
EMAC[0]_RXD1: RU95.47(4B1) ; also on sheet 56
EMAC[0]_RXD2: RU95.45(5B1) ; also on sheet 56
EMAC[0]_RXD3: RU95.43(6B1) ; also on sheet 56
EMAC[0]_TXC: RU95.30(12B1) ; also on sheet 56
EMAC[0]_TXCTL: RU95.32(11B1) ; also on sheet 56
EMAC[0]_TXD0: RU95.41(7B1) ; also on sheet 56
EMAC[0]_TXD1: RU95.39(8B1) ; also on sheet 56
EMAC[0]_TXD2: RU95.36(9B1) ; also on sheet 56
EMAC[0]_TXD3: RU95.34(10B1) ; also on sheet 56
ENET_INTSn: U52.F21(GPIO6_16) ; also on sheet 56
EVM_3V3: C98.1 C122.1 C129.1 C135.1 C296.1 C311.1 C315.1 C323.1 C383.1 C428.1 C488.1 C513.2 C523.2 C692.1 R229.1 R233.1 R240.1 R246.1 R264.1 R268.1 R270.1 R469.1 R573.1 R575.1 R577.1 R618.1 R622.1 R624.1 R629.1 R633.1 R652.1 R755.1 RU29.5(VCC) RU49.20(VCC) RU89.16(VCC) RU95.17(VCC.1) RU99.17(VCC.1) RU103.20(VCC) RU108.16(VCC) RU111.16(VCC) RU113.16(VCC) U28.5(VCC) U105.8(VCC) U106.5(VCC) U109.5(V+) U117.5(V+) U120.5(VCC) U121.5(VCC) ; also on sheet 3 4 5 7 8 9 10 11 14 15 16 17 18 24 25 26 27 28 29 30 31 32 33 49 50 51 52 53 56 57 58 60 61 69 70 78
GP5[22]: RU95.33(10B2) ; also on sheet 60
GP5[25]: RU95.40(7B2) ; also on sheet 60
GP5[29]: RU95.44(5B2) ; also on sheet 60
GP5[30]: RU95.46(4B2) ; also on sheet 60
GP5[31]: RU95.48(3B2) ; also on sheet 60
GP6_[28]: U52.Y9(MMC1_SDWP) ; also on sheet 11
HDMI_DSCL: RU108.6(2B2) ; also on sheet 27
HDMI_DSDA: RU108.3(1B2) ; also on sheet 27
I2C1_SCL: R618.2 U52.C20(I2C1_SCL) U105.6(SCL) U109.1(SCL) U117.1(SCL) ; also on sheet 9 11 26 53 55 61
I2C1_SDA: R624.2 U52.C21(I2C1_SDA) U105.5(SDA) U109.6(SDA) U117.6(SDA) ; also on sheet 9 11 26 53 55 61
I2C2_SCL: R233.2 RU108.2(1B1) ; also on sheet 9 28 29 62
I2C2_SDA: R240.2 RU108.5(2B1) ; also on sheet 9 28 29 62
I2C3_SCL: R270.2 RU113.5(2B1) ; also on sheet 60
I2C3_SDA: R268.2 RU113.2(1B1) ; also on sheet 60
I2C_EEPROM_WP: U105.7(WP) ; also on sheet 18
MCA1_ACLKX: RU49.14(B5) ; also on sheet 52
MCA1_AFSX: RU49.13(B6) ; also on sheet 52
MCA1_AXR0: RU99.33(10B2) ; also on sheet 52
MCA1_AXR1: RU99.31(11B2) ; also on sheet 52
MCA2_ACLKX: RU99.44(5B2) ; also on sheet 61
MCA2_AFSX: RU49.12(B7) ; also on sheet 61
MCA2_AXR0: RU103.18(B1) ; also on sheet 61
MCA2_AXR1: RU103.17(B2) ; also on sheet 61
MCA2_AXR2: RU103.16(B3) ; also on sheet 61
MCA2_AXR3: RU103.15(B4) ; also on sheet 61
MCA2_AXR4: RU103.14(B5) ; also on sheet 61
MCA2_AXR5: RU103.13(B6) ; also on sheet 61
MCA2_AXR6: RU103.12(B7) ; also on sheet 61
MCA2_AXR7: RU103.11(B8) ; also on sheet 61
MCA6_ACLKX: RU49.17(B2) ; also on sheet 61
MCA6_AFSX: RU49.18(B1) ; also on sheet 61
MCA6_AHCLKX: RU29.4(O) ; also on sheet 61
MCA6_AXR0: RU49.16(B3) ; also on sheet 61
MCA6_AXR1: RU49.15(B4) ; also on sheet 61
MCA7_AXR0: RU99.35(9B2) ; also on sheet 52
MCA7_AXR1: RU99.37(8B2) ; also on sheet 52
MCA7_CLKX: RU99.40(7B2) ; also on sheet 52
MCA7_FSX: RU99.42(6B2) ; also on sheet 52
MDIO_MDCLK: RU89.2(1B1) ; also on sheet 56 57
MDIO_MDIO: RU89.5(2B1) ; also on sheet 56 57
MMC1_CLK: R510.1 ; also on sheet 10
MMC1_CMD: U52.Y6(MMC1_CMD) ; also on sheet 10
MMC1_DAT0: U52.AA6(MMC1_DAT0) ; also on sheet 10
MMC1_DAT1: U52.Y4(MMC1_DAT1) ; also on sheet 10
MMC1_DAT2: U52.AA5(MMC1_DAT2) ; also on sheet 10
MMC1_DAT3: U52.Y3(MMC1_DAT3) ; also on sheet 10
MMC1_SD_CD: U52.W7(MMC1_SDCD) ; also on sheet 10
MMC3_CLK: R512.1 ; also on sheet 62
MMC3_CMD: U52.AC4(MMC3_CMD) ; also on sheet 62
MMC3_DAT0: U52.AC7(MMC3_DAT0) ; also on sheet 62
MMC3_DAT1: U52.AC6(MMC3_DAT1) ; also on sheet 62
MMC3_DAT2: U52.AC9(MMC3_DAT2) ; also on sheet 62
MMC3_DAT3: U52.AC3(MMC3_DAT3) ; also on sheet 62
MMC3_DAT4: U52.AC8(MMC3_DAT4) ; also on sheet 62
MMC3_DAT5: U52.AD6(MMC3_DAT5) ; also on sheet 62
MMC3_DAT6: U52.AB8(MMC3_DAT6) ; also on sheet 62
MMC3_DAT7: U52.AB5(MMC3_DAT7) ; also on sheet 62
MMC4_CLK: R651.1 ; also on sheet 52
MMC4_CMD: U52.C27(UART1_RTSN) ; also on sheet 52
MMC4_DAT0: U52.D28(UART2_RXD) ; also on sheet 52
MMC4_DAT1: U52.D26(UART2_TXD) ; also on sheet 52
MMC4_DAT2: R776.2 U52.D27(UART2_CTSN) ; also on sheet 52
MMC4_DAT3: R777.2 U52.C28(UART2_RTSN) ; also on sheet 52
PCF8575_INT: U52.AB4(GPIO6_11) ; also on sheet 9
PCIE_RXN0: R78.1 U52.AG13(PCIE_RXN0)
PCIE_RXP0: R77.1 U52.AH13(PCIE_RXP0)
PCIE_TXN0: C65.1 U52.AG14(PCIE_TXN0)
PCIE_TXP0: C64.1 U52.AH14(PCIE_TXP0)
POWERHOLD_CLK: R824.1 ; also on sheet 79
RC_MMC1_CLK: R510.2 U52.W6(MMC1_CLK)
RC_MMC3_CLK: R512.2 U52.AD4(MMC3_CLK)
SATA_RXN0: C70.2 U52.AH9(SATA1_RXN0)
SATA_RXP0: C68.2 U52.AG9(SATA1_RXP0)
SATA_TXN0: C73.2 U52.AG10(SATA1_TXN0)
SATA_TXP0: C75.2 U52.AH10(SATA1_TXP0)
SEL_ENET_MUX_S0: R469.2 RU95.1(S0) U28.2(I) ; also on sheet 9
SEL_ENET_MUX_S1: RU89.1(S) RU95.56(S1) U28.4(O)
SEL_HDMI_I2C2: R229.2 R230.1 RU108.1(S) ; also on sheet 2
SEL_I2C3_CAN2: R264.2 R265.1 RU113.1(S) ; also on sheet 9
SEL_UART3_SPI2: R246.2 R247.1 RU111.1(S) ; also on sheet 9
SERDES_CLKN: C125.1 R223.2 R807.1 U52.AH15(LJCB_CLKN)
SERDES_CLKP: C120.1 R223.1 R806.1 U52.AG15(LJCB_CLKP)
SERDES_IN_REFN: C125.2 ; also on sheet 30
SERDES_IN_REFP: C120.2 ; also on sheet 30
SPI[1]_CS[0]n: R641.1 ; also on sheet 62
SPI[1]_CS[1]n: U52.A22(SPI1_CS1) ; also on sheet 62 70
SPI[1]_MISO: R614.1 ; also on sheet 62
SPI[1]_MOSI: R657.1 ; also on sheet 62
SPI[1]_SCLK: R258.1 ; also on sheet 62
SPI[2]_CS[0]n: RU111.13(4B2) ; also on sheet 62
SPI[2]_MISO: RU111.6(2B2) ; also on sheet 62
SPI[2]_MOSI: RU111.10(3B2) ; also on sheet 62
SPI[2]_SCLK: RU111.3(1B2) ; also on sheet 62
TMP102_ALERT: U109.3(ALERT) U117.3(ALERT) ; also on sheet 9
UART1_RXD: U52.B27(UART1_RXD) ; also on sheet 51
UART1_TXD: U52.C26(UART1_TXD) ; also on sheet 51
UART3_CTS: RU111.11(3B1) ; also on sheet 52
UART3_RTS: RU111.14(4B1) ; also on sheet 52
UART3_RXD: RU111.2(1B1) ; also on sheet 52
UART3_RXD_BOOT: R776.1 ; also on sheet 51
UART3_TXD: RU111.5(2B1) ; also on sheet 52
UART3_TXD_BOOT: R777.1 ; also on sheet 51
WAKE_UP_CAN: R232.2 ; also on sheet 33
N17119566: R611.2 R824.2 U52.G19(DCAN1_RX)
N18150170: R723.1 RU95.3(1A2) RU95.5(2A2) RU95.7(3A2) RU95.10(4A2) RU95.12(5A2) RU95.14(6A2) RU95.16(7A2) RU95.20(8A2) RU95.22(9A2) RU95.24(10A2) RU95.26(11A2) RU95.28(12A2)
N18150546: R724.1 RU99.3(1A2) RU99.5(2A2) RU99.7(3A2) RU99.10(4A2) RU99.12(5A2) RU99.14(6A2) RU99.16(7A2) RU99.20(8A2) RU99.22(9A2) RU99.24(10A2) RU99.26(11A2) RU99.27(12A1) RU99.28(12A2)
N18474602: R755.2 U120.1(OE) U121.1(OE)
N18474703: U52.A25(SPI1_SCLK) U120.2(I) U121.2(I)
N18474722: R658.2 U120.4(O)
N18474725: R258.2 U121.4(O)
N28297494: TP37.1 U52.Y5(MMC1_BIAS)
N29597106: R577.2 R578.1 U105.1(A0)
N29597110: R575.2 R576.1 U105.2(A1)
N29597116: R573.2 R574.1 U105.3(NC)
N29654001: R248.2 R641.2 U52.A24(SPI1_CS0)
N29675465: R625.1 R629.2 U109.4(ADD0) U117.4(ADD0)
N29685204: R259.2 R657.2 U52.B25(SPI1_D0)
N29687998: R235.2 R614.2 U52.F16(SPI1_D1)
N30484351: R261.2 U52.A26(SPI2_SCLK)
N33175207: RU99.56(S1) U106.4(O)
N36181317: R651.2 U52.E25(UART1_CTSN)

Not connected (* = marked no-connect by the designer): J11 8(MH1)* 9(MH9)*; RU49 1(NC)* 9(A8) 11(B8); RU89 11(3B1) 14(4B1); RU99 29(12B2) 30(12B1); RU103 1(NC)*; RU108 9(3A) 10(3B2) 11(3B1) 12(4A) 13(4B2) 14(4B1); RU113 10(3B2) 11(3B1) 13(4B2) 14(4B1); U28 1(NC1); U52 AG11(PCIE_RXN1) AG12(PCIE_TXN1) AH11(PCIE_RXP1) AH12(PCIE_TXP1); U106 1(NC1)

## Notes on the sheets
sheet 83
- mmc3_clk
  mmc3_cmd
  mmc3_dat[0]
  mmc3_dat[1]
  mmc3_dat[2]
  mmc3_dat[3]
  mmc3_dat[4]
  mmc3_dat[5]
  mmc3_dat[6]
  mmc3_dat[7]
- vin5a_d[7]
  vin5a_d[6]
  vin5a_d[5]
  vin5a_d[4]
  vin5a_d[3]
  vin5a_d[2]
  vin5a_d[1]
  vin5a_d[0]
  vin5a_hsync0
  vin5a_vsync0
sheet 84
- i2c2_sda
  i2c2_scl
- hdmi1_ddc_scl
  hdmi1_ddc_sda
- REV D
- spi1_cs[2]
  spi1_cs[3]
- mmc3_sdcd
  mmc3_sdwp
- hdmi1_hpd
  hdmi1_cec
- REV E
- REV E
- DCAN2 signaling is not SW controllable.
  Requires HW change: R264 = 10k & R265 =
  NO-POP
- spi2_sclk
  spi2_d[1]
  spi2_d[0]
  spi2_cs[0]
- uart3_rxd
  uart3_txd
  uart3_ctsn
  uart3_rtsn
sheet 85
- FUNCTION TABLE
  INPUTS      INPUTS/OUTPUTS        FUNCTION
  S2 S1 S0          A1 A2
  L L L             Z Z               Disconnect
  L L H             B1 Z          A1 port = B1 port
  L H L             B2 Z          A1 port = B2 port
  L H H             Z B1          A2 port = B1 port
  H L L             Z B2          A2 port = B2 port
  H L H             Z Z           Disconnect
  H H L             B1 B2         A1 port = B1 port
                                  A2 port = B2 port
  H H H             B2 B1         A1 port = B2 port
                                  A2 port = B1 port
- mdio_mclk
  mdio_d
  RMII_MHZ_50_CLK
  uart3_rxd
  uart3_txd
  rgmii0_txc
  rgmii0_txctl
  rgmii0_txd[3]
  rgmii0_txd[2]
  rgmii0_txd[1]
  rgmii0_txd[0]
  rgmii0_rxc
  rgmii0_rxctl
  rgmii0_rxd[3]
  rgmii0_rxd[2]
  rgmii0_rxd[1]
  rgmii0_rxd[0]
- vin4b_clk1
  vin4b_d[0]
  vin4b_d[1]
  vin4b_d[2]
  vin4b_d[3]
  vin4b_d[4]
  vin4b_de1
  vin4b_hsync1
  vin4b_vsync1
  vin4b_d[5]
  vin4b_d[6]
  vin4b_d[7]
  vin4b_fld1
- gpio5_15
  gpio5_16
  gpio5_17
  gpio5_18
  gpio5_19
  gpio5_20
  gpio5_21
  gpio5_22
  gpio5_23
  gpio5_24
  gpio5_25
  gpio5_26
  gpio5_27
  gpio5_28
  gpio5_29
  gpio5_30
  gpio5_31
sheet 86
- FUNCTION TABLE
  INPUTS      INPUTS/OUTPUTS        FUNCTION
  S2 S1 S0          A1 A2
  L L L             Z Z               Disconnect
  L L H             B1 Z          A1 port = B1 port
  L H L             B2 Z          A1 port = B2 port
  L H H             Z B1          A2 port = B1 port
  H L L             Z B2          A2 port = B2 port
  H L H             Z Z           Disconnect
  H H L             B1 B2         A1 port = B1 port
                                  A2 port = B2 port
  H H H             B2 B1         A1 port = B2 port
                                  A2 port = B1 port
- mcasp3_aclkx
  mcasp3_fsx
  mcasp3_axr[0]
  mcasp3_axr[1]
- vin6a_d[3]
  vin6a_d[2]
  vin6a_d[1]
  vin6a_d[0]
- mcasp2_aclkx
  mcasp2_fsx
  mcasp2_aclkr
  mcasp2_fsr
  mcasp2_axr[0]
  mcasp2_axr[1]
  mcasp2_axr[2]
  mcasp2_axr[3]
  mcasp2_axr[4]
  mcasp2_axr[5]
  mcasp2_axr[6]
  mcasp2_axr[7]
- vin6a_d[7]
  vin6a_d[6]
  vin6a_d[5]
  vin6a_d[4]
- mcasp1_axr[12]
  mcasp1_axr[13]
  mcasp1_axr[14]
  mcasp1_axr[15]
- mcasp7_axr[0]
  mcasp7_axr[1]
  mcasp7_aclkx
  mcasp7_fsx
- vin6a_d[11]
  vin6a_d[10]
  vin6a_d[9]
  vin6a_d[8]
- mcasp1_aclkx
  mcasp1_fsx
  mcasp1_aclkr
  mcasp1_fsr
  mcasp1_axr[0]
  mcasp1_axr[1]
- vin6a_fld0
  vin6a_de0
  vin6a_vsync0
  vin6a_hsync0
- mcasp1_axr[8]
  mcasp1_axr[9]
  mcasp1_axr[10]
  mcasp1_axr[11]
  mcasp1_axr[12]
  mcasp1_axr[13]
  mcasp1_axr[14]
  mcasp1_axr[15]
- mcasp6_axr[0]
  mcasp6_axr[1]
  mcasp6_aclkx
  mcasp6_fsx
  mcasp7_axr[0]
  mcasp7_axr[1]
  mcasp7_aclkx
  mcasp7_fsx
- vin6a_d[15]
  vin6a_d[14]
  vin6a_d[13]
  vin6a_d[12]
  vin6a_d[11]
  vin6a_d[10]
  vin6a_d[9]
  vin6a_d[8]
- MCA6_AHCLKX
- xref_clk1
- mcasp6_ahclkx
- vin6a_clk0
sheet 87
- ER14
- gpio6_14
  gpio6_15
- dcan2_tx
  dcan2_rx
- spi2_sclk
  spi2_d[1]
  spi2_d[0]
  spi2_cs[0]
- uart3_rxd
  uart3_txd
  uart3_ctsn
  uart3_rtsn
- spi1_cs[2]
  spi1_cs[3]
- mmc3_sdcd
  mmc3_sdwp
- hdmi1_hpd
  hdmi1_cec
- REV D
- uart1_ctsn
  uart1_rtsn
- mmc4_clk
  mmc4_cmd
- uart2_rxd
  uart2_txd
  uart2_ctsn
  uart2_rtsn
- mmc4_dat[0]
  mmc4_dat[1]
  mmc4_dat[2]
  mmc4_dat[3]
- 50 OHMS FOR R776 AND R777 WHEN POPULATED
  BASED ON SIMULATION
- REV D
- i2c2_sda
  i2c2_scl
- hdmi1_ddc_scl
  hdmi1_ddc_sda
sheet 88
- PLACE TEMP SENSOR CLOSE TO PROCESSOR
- Preliminary Information - Subject to change
sheet 89
- 1.8 VOLT
- 1.8 VOLT
- DIFFERENTIAL PAIR
  100 OHM DIFFERENTIAL
  IMPEDANCE
  SHORT AND STRAIGHT AS
  POSSIBLE,
  MINIMUM NUMBER OF VIAS
- AC COUPLING CAP
  PLACE BY CONNECTOR
- Pin # Function
  1 Ground
  2 A+ (Transmit)
  3 A- (Transmit)
  4 Ground
  5 B- (Receive)
  6 B+ (Receive)
  7 Ground
  - coding notch
  A 7-pin Serial ATA data cable
- REV D
- REV E
- AC COUPLING CAP
  PLACE BY CONNECTOR
- DIFFERENTIAL PAIR
  100 OHM DIFFERENTIAL
  IMPEDANCE
  SHORT AND STRAIGHT AS
  POSSIBLE,
  MINIMUM NUMBER OF VIAS
- ER25
- DIFFERENTIAL PAIR
  XXXX OHM DIFFERENTIAL
  IMPEDANCE
  SHORT AND STRAIGHT AS
  POSSIBLE,
  MINIMUM NUMBER OF VIAS
